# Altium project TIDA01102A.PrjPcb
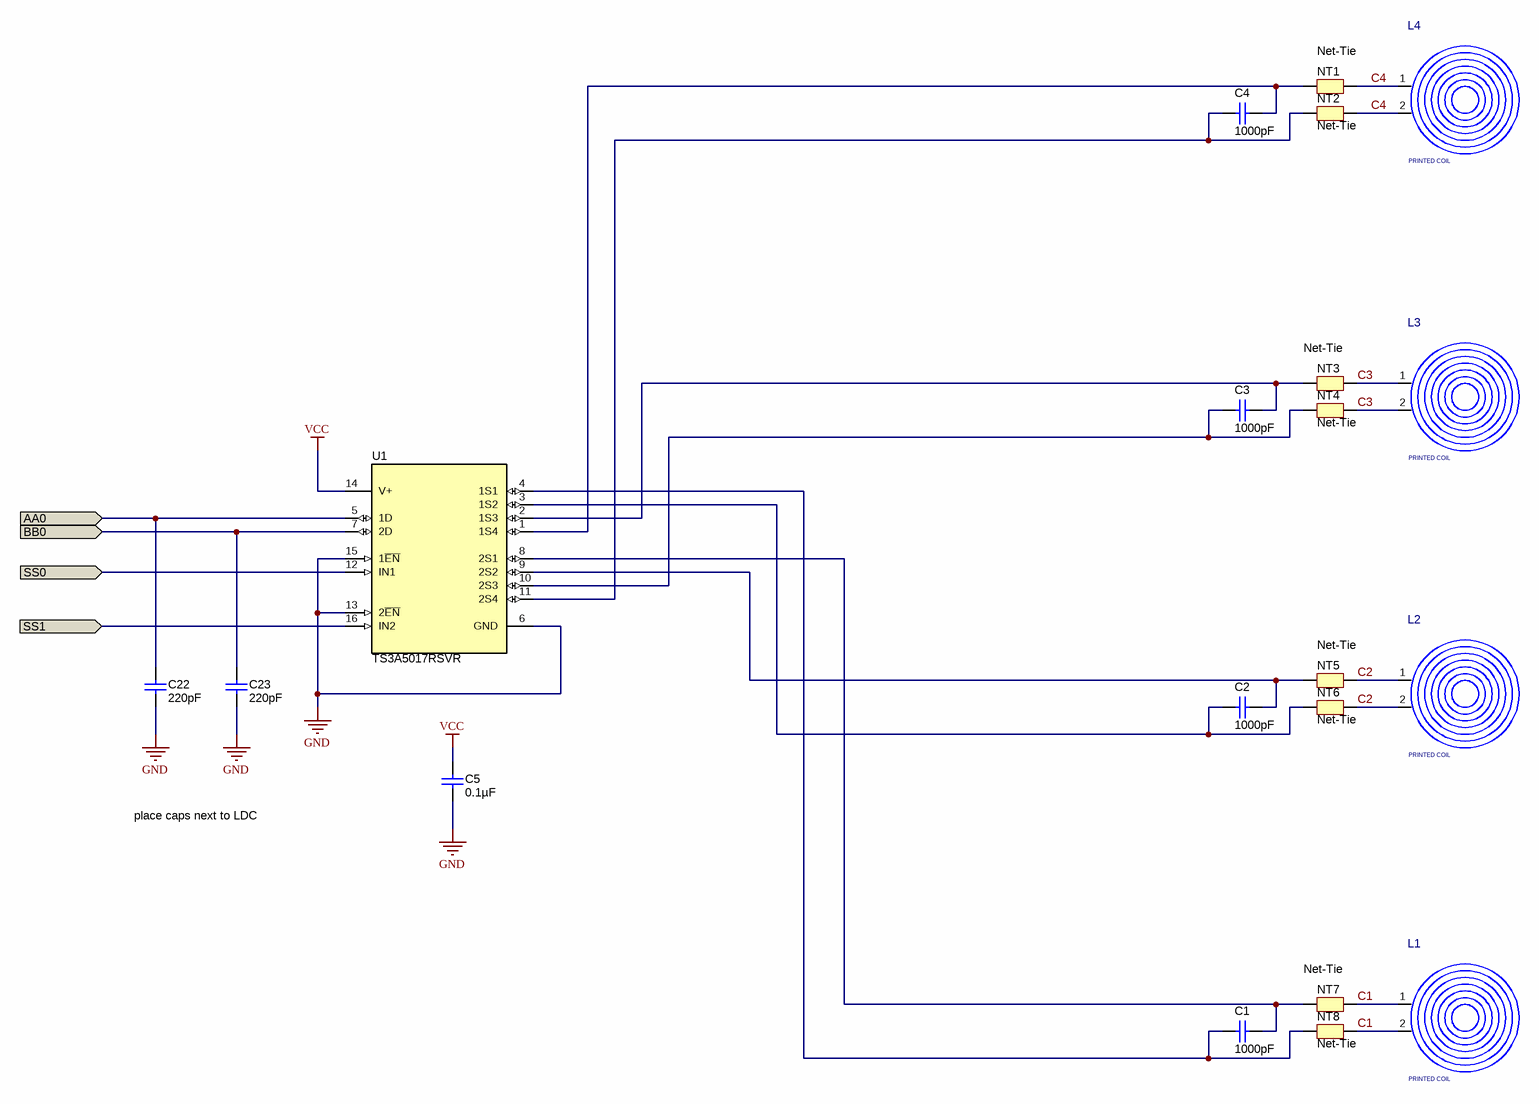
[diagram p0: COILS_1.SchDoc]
TID: TIDA-01102; TechSupport: http://www.ti.com/support; SCH_Rev: A; PRJ_Title: TOM 16 button; PRJ_Number: TIDA-01102; PRJ_Engineer: L. Lapointe; PRJ_Customer: For Public Release; PCB_Rev: A; PCB_Layout: K. Clanin; CopyrightYear: 2016
9 sheets, 177 parts. Net scope: flat (ports and power ports of the same name join across sheets).
Board file: TIDA-01102A.PcbDoc
Sheets:
  COILS_1.SchDoc
  COILS_2.SchDoc
  COILS_3.SchDoc
  COILS_4.SchDoc
  LDC_CLOCK.SchDoc
  LED_ARRAY.SchDoc
  UCONTROLLER.SchDoc
  TIDA-01102A_COVER.SchDoc
  TIDA-01102A_Hardware.SchDoc

## Sheet COILS_1.SchDoc
size 431 x 279 mm; Date: Not shown in title block; ApprovedBy: Not shown in title block; CheckedBy: Not shown in title block; Author: Not shown in title block; CompanyName: Not shown in title block; Engineer: Not shown in title block; Organization: Not shown in title block; Address1: Not shown in title block; Address2: Not shown in title block; Address3: Not shown in title block; Address4: Not shown in title block; DocumentNumber: 1; Revision: Use project parameter SCH_Rev; SheetNumber: 5; SheetTotal: 9; PageSetup: Record=PageOptions¦CenterHorizontal=True¦CenterVertical=True¦PrintScale=1.00¦XCorrection=1.00¦YCorrection=1.00¦PrintKind=0¦BorderSize=5000000¦LeftOffset=0¦BottomOffset=0¦Orientation=2¦PaperLength=1000¦PaperWidth=1000¦Scale=100¦PaperSource=15¦PrintQuality=600¦MediaType=1¦DitherType=10¦PaperKind=Letter¦PrintScaleMode=1

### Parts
C1  ValueDisplayed: 1000pF  [0402]  (hidden comment: GRM155R71H102KA01D)
C2  ValueDisplayed: 1000pF  [0402]  (hidden comment: GRM155R71H102KA01D)
C3  ValueDisplayed: 1000pF  [0402]  (hidden comment: GRM155R71H102KA01D)
C4  ValueDisplayed: 1000pF  [0402]  (hidden comment: GRM155R71H102KA01D)
C5  ValueDisplayed: 0.1µF  [0402]  (hidden comment: C1005X7R1H104K050BB)
C22  ValueDisplayed: 220pF  [0402]  (hidden comment: GRM155R71H221KA01D)
C23  ValueDisplayed: 220pF  [0402]  (hidden comment: GRM155R71H221KA01D)
L1  PRINTED COIL  [PRINTED_COIL_8.2MM_AIR_HOLE]
L2  PRINTED COIL  [PRINTED_COIL_8.2MM_AIR_HOLE]
L3  PRINTED COIL  [PRINTED_COIL_8.2MM_AIR_HOLE]
L4  PRINTED COIL  [PRINTED_COIL_8.2MM_AIR_HOLE]
NT1  Net-Tie  [Net-Tie_10mil]  (net tie, no BOM)
NT2  Net-Tie  [Net-Tie_10mil]  (net tie, no BOM)
NT3  Net-Tie  [Net-Tie_10mil]  (net tie, no BOM)
NT4  Net-Tie  [Net-Tie_10mil]  (net tie, no BOM)
NT5  Net-Tie  [Net-Tie_10mil]  (net tie, no BOM)
NT6  Net-Tie  [Net-Tie_10mil]  (net tie, no BOM)
NT7  Net-Tie  [Net-Tie_10mil]  (net tie, no BOM)
NT8  Net-Tie  [Net-Tie_10mil]  (net tie, no BOM)
U1  TS3A5017RSVR  [RSV0016A]

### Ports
AA0 (in), BB0 (in), SS0 (in), SS1 (in)

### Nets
GND: C5.2 C22.1 C23.1 U1.6(GND) U1.13(2~{EN}) U1.15(1~{EN})
VCC: C5.1 U1.14(V+)
AA0: C22.2 U1.5(1D) ; port AA0
BB0: C23.2 U1.7(2D) ; port BB0
C1: L1.1(.) L1.2(.) NT7.2 NT8.2
C2: L2.1(.) L2.2(.) NT5.2 NT6.2
C3: L3.1(.) L3.2(.) NT3.2 NT4.2
C4: L4.1(.) L4.2(.) NT1.2 NT2.2
SS0: U1.12(IN1) ; port SS0
SS1: U1.16(IN2) ; port SS1
NetC1_1: C1.1 NT8.1 U1.4(1S1)
NetC1_2: C1.2 NT7.1 U1.8(2S1)
NetC2_1: C2.1 NT6.1 U1.3(1S2)
NetC2_2: C2.2 NT5.1 U1.9(2S2)
NetC3_1: C3.1 NT4.1 U1.10(2S3)
NetC3_2: C3.2 NT3.1 U1.2(1S3)
NetC4_1: C4.1 NT2.1 U1.11(2S4)
NetC4_2: C4.2 NT1.1 U1.1(1S4)

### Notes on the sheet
- place caps next to LDC

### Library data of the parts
C1-C4 = GRM155R71H102KA01D: CAP, CERM, 1000 pF, 50 V, +/- 10%, X7R, 0402; Manufacturer: MuRata; Polarized: N; CompType: Capacitor; Value: 1000pF; U/M: EA; Cap_F: 0.000000001; Tolerance_%: 10; Value1: Unknown; VDC_V: 50; Value2: 50V; TaMin_C: -55; TaMax_C: 125; AEC Category: Q200; SizeArea_mm2: 0.5; SizeAreaWB_mm2: 3; SizeX_mm: 1; SizeZ_mm: 0.6
C5 = C1005X7R1H104K050BB: CAP, CERM, 0.1 µF, 50 V, +/- 10%, X7R, 0402; Manufacturer: TDK; Polarized: N; CompType: Capacitor; U/M: EA; Cap_F: 0.0000001; Tolerance_%: 10; ESR_ohm: 0.039064; VDC_V: 50; IRMS_A: 0.814669; TaMin_C: -55; TaMax_C: 125; Value: 0.1uF; Value1: 0.039064 ohm; Value2: 50V; AEC Category: Q200; SizeArea_mm2: 0.5; SizeAreaWB_mm2: 3; SizeX_mm: 1; SizeZ_mm: 0.6
C22 C23 = GRM155R71H221KA01D: CAP, CERM, 220 pF, 50 V, +/- 10%, X7R, 0402; Manufacturer: MuRata; Polarized: N; CompType: Capacitor; Value: 220pF; U/M: EA; Cap_F: 0.00000000022; Tolerance_%: 10; Value1: Unknown; VDC_V: 50; Value2: 50V; TaMin_C: -55; TaMax_C: 125; AEC Category: Q200; SizeArea_mm2: 0.5; SizeAreaWB_mm2: 3; SizeX_mm: 1; SizeZ_mm: 0.6
L1-L4 = PRINTED COIL: 8.2MM 2-layer Coil 3.5uH
NT1-NT8 = Net-Tie: Single point connection between nets.; SymbolCreator: codlsc
U1 = TS3A5017RSVR: 14-Ohm Dual SP4T Analog Switch 3.3-V/2.5-V Analog Multiplexer/Demultiplexer, RSV0016A (UQFN-16); Manufacturer: Texas Instruments; SymbolCreator: Altium; CompType: IC; U/M: EA; SizeArea_mm2: 4.68; SizeAreaWB_mm2: 10.08; SizeX_mm: 1.8; SizeY_mm: 2.6; SizeZ_mm: 0.55

## Sheet COILS_2.SchDoc
size 431 x 279 mm; Date: Not shown in title block; ApprovedBy: Not shown in title block; CheckedBy: Not shown in title block; Author: Not shown in title block; CompanyName: Not shown in title block; Engineer: Not shown in title block; Organization: Not shown in title block; Address1: Not shown in title block; Address2: Not shown in title block; Address3: Not shown in title block; Address4: Not shown in title block; DocumentNumber: 1; Revision: Use project parameter SCH_Rev; SheetNumber: 6; SheetTotal: 9; PageSetup: Record=PageOptions¦CenterHorizontal=True¦CenterVertical=True¦PrintScale=1.00¦XCorrection=1.00¦YCorrection=1.00¦PrintKind=0¦BorderSize=5000000¦LeftOffset=0¦BottomOffset=0¦Orientation=2¦PaperLength=1000¦PaperWidth=1000¦Scale=100¦PaperSource=15¦PrintQuality=600¦MediaType=1¦DitherType=10¦PaperKind=Letter¦PrintScaleMode=1
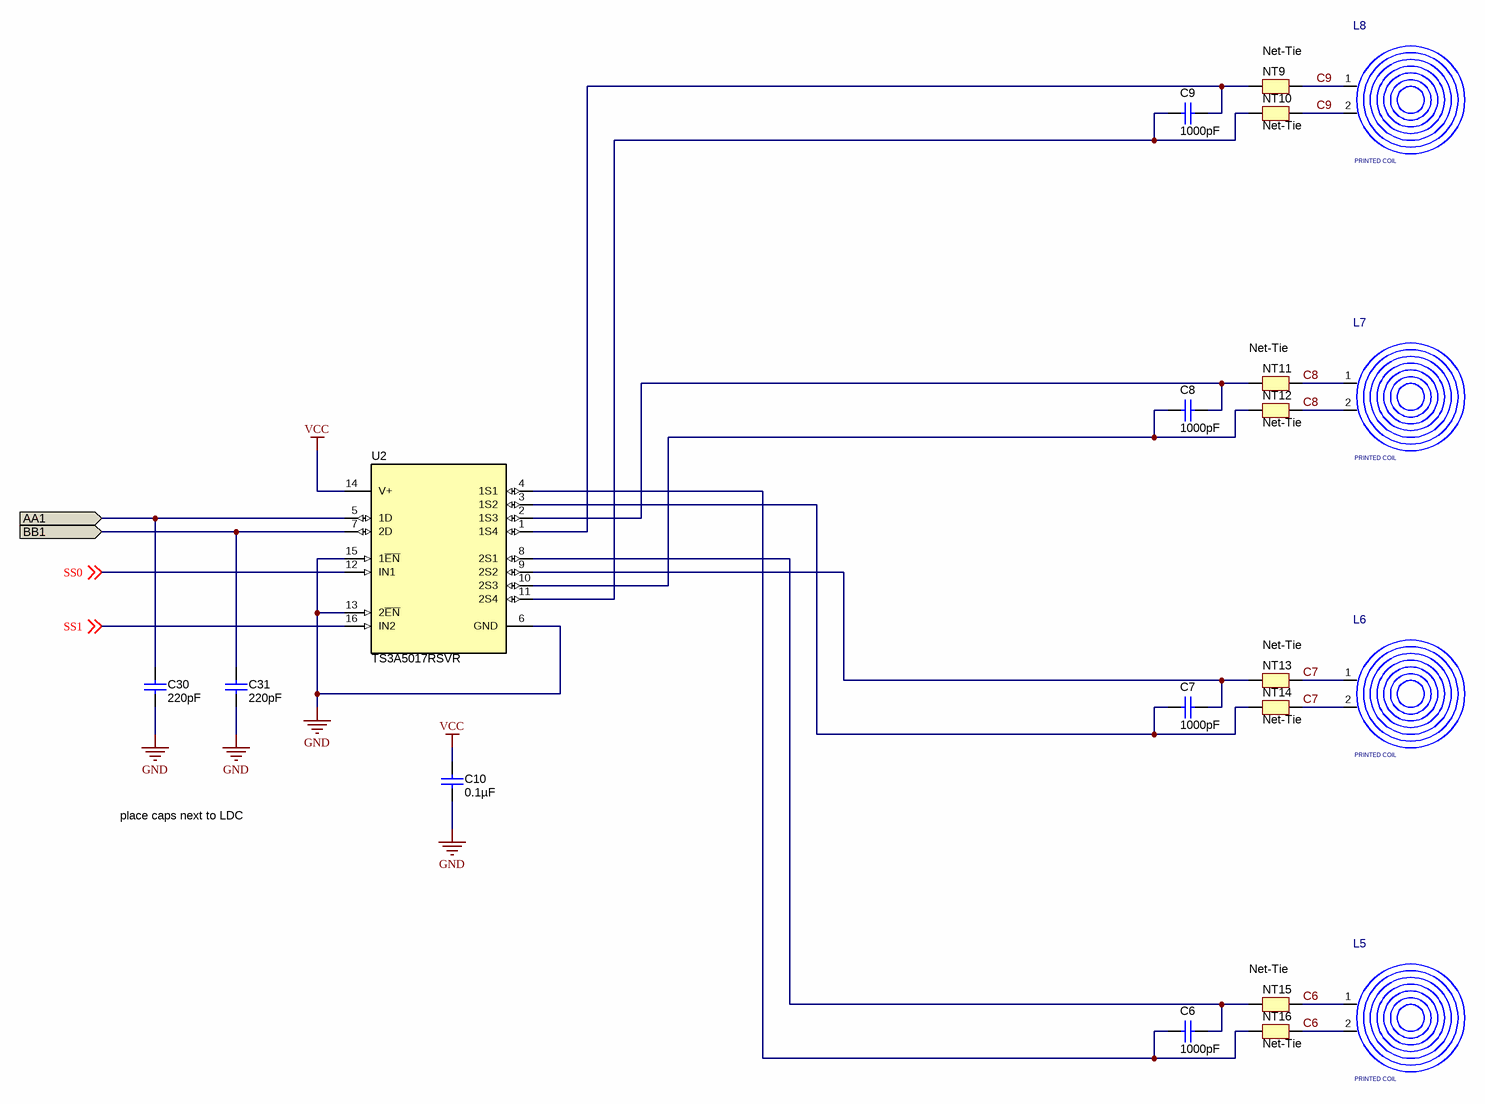
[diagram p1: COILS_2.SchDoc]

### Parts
C6  ValueDisplayed: 1000pF  [0402]  (hidden comment: GRM155R71H102KA01D)
C7  ValueDisplayed: 1000pF  [0402]  (hidden comment: GRM155R71H102KA01D)
C8  ValueDisplayed: 1000pF  [0402]  (hidden comment: GRM155R71H102KA01D)
C9  ValueDisplayed: 1000pF  [0402]  (hidden comment: GRM155R71H102KA01D)
C10  ValueDisplayed: 0.1µF  [0402]  (hidden comment: C1005X7R1H104K050BB)
C30  ValueDisplayed: 220pF  [0402]  (hidden comment: GRM155R71H221KA01D)
C31  ValueDisplayed: 220pF  [0402]  (hidden comment: GRM155R71H221KA01D)
L5  PRINTED COIL  [PRINTED_COIL_8.2MM_AIR_HOLE]
L6  PRINTED COIL  [PRINTED_COIL_8.2MM_AIR_HOLE]
L7  PRINTED COIL  [PRINTED_COIL_8.2MM_AIR_HOLE]
L8  PRINTED COIL  [PRINTED_COIL_8.2MM_AIR_HOLE]
NT9  Net-Tie  [Net-Tie_10mil]  (net tie, no BOM)
NT10  Net-Tie  [Net-Tie_10mil]  (net tie, no BOM)
NT11  Net-Tie  [Net-Tie_10mil]  (net tie, no BOM)
NT12  Net-Tie  [Net-Tie_10mil]  (net tie, no BOM)
NT13  Net-Tie  [Net-Tie_10mil]  (net tie, no BOM)
NT14  Net-Tie  [Net-Tie_10mil]  (net tie, no BOM)
NT15  Net-Tie  [Net-Tie_10mil]  (net tie, no BOM)
NT16  Net-Tie  [Net-Tie_10mil]  (net tie, no BOM)
U2  TS3A5017RSVR  [RSV0016A]

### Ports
AA1 (in), BB1 (in)

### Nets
GND: C10.2 C30.1 C31.1 U2.6(GND) U2.13(2~{EN}) U2.15(1~{EN})
VCC: C10.1 U2.14(V+)
AA1: C30.2 U2.5(1D) ; port AA1
BB1: C31.2 U2.7(2D) ; port BB1
C6: L5.1(.) L5.2(.) NT15.2 NT16.2
C7: L6.1(.) L6.2(.) NT13.2 NT14.2
C8: L7.1(.) L7.2(.) NT11.2 NT12.2
C9: L8.1(.) L8.2(.) NT9.2 NT10.2
SS0: U2.12(IN1) ; off-sheet SS0
SS1: U2.16(IN2) ; off-sheet SS1
NetC6_1: C6.1 NT16.1 U2.4(1S1)
NetC6_2: C6.2 NT15.1 U2.8(2S1)
NetC7_1: C7.1 NT14.1 U2.3(1S2)
NetC7_2: C7.2 NT13.1 U2.9(2S2)
NetC8_1: C8.1 NT12.1 U2.10(2S3)
NetC8_2: C8.2 NT11.1 U2.2(1S3)
NetC9_1: C9.1 NT10.1 U2.11(2S4)
NetC9_2: C9.2 NT9.1 U2.1(1S4)

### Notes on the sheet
- place caps next to LDC

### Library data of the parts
C6-C9 = GRM155R71H102KA01D: as C1 on sheet COILS_1
C10 = C1005X7R1H104K050BB: as C5 on sheet COILS_1
C30 C31 = GRM155R71H221KA01D: as C22 on sheet COILS_1
L5-L8 = PRINTED COIL: 8.2MM 2-layer Coil 3.5uH
NT9-NT16 = Net-Tie: as NT1 on sheet COILS_1
U2 = TS3A5017RSVR: as U1 on sheet COILS_1

## Sheet COILS_3.SchDoc
size 431 x 279 mm; Date: Not shown in title block; ApprovedBy: Not shown in title block; CheckedBy: Not shown in title block; Author: Not shown in title block; CompanyName: Not shown in title block; Engineer: Not shown in title block; Organization: Not shown in title block; Address1: Not shown in title block; Address2: Not shown in title block; Address3: Not shown in title block; Address4: Not shown in title block; DocumentNumber: 1; Revision: Use project parameter SCH_Rev; SheetNumber: 7; SheetTotal: 9; PageSetup: Record=PageOptions¦CenterHorizontal=True¦CenterVertical=True¦PrintScale=1.00¦XCorrection=1.00¦YCorrection=1.00¦PrintKind=0¦BorderSize=5000000¦LeftOffset=0¦BottomOffset=0¦Orientation=2¦PaperLength=1000¦PaperWidth=1000¦Scale=100¦PaperSource=15¦PrintQuality=600¦MediaType=1¦DitherType=10¦PaperKind=Letter¦PrintScaleMode=1
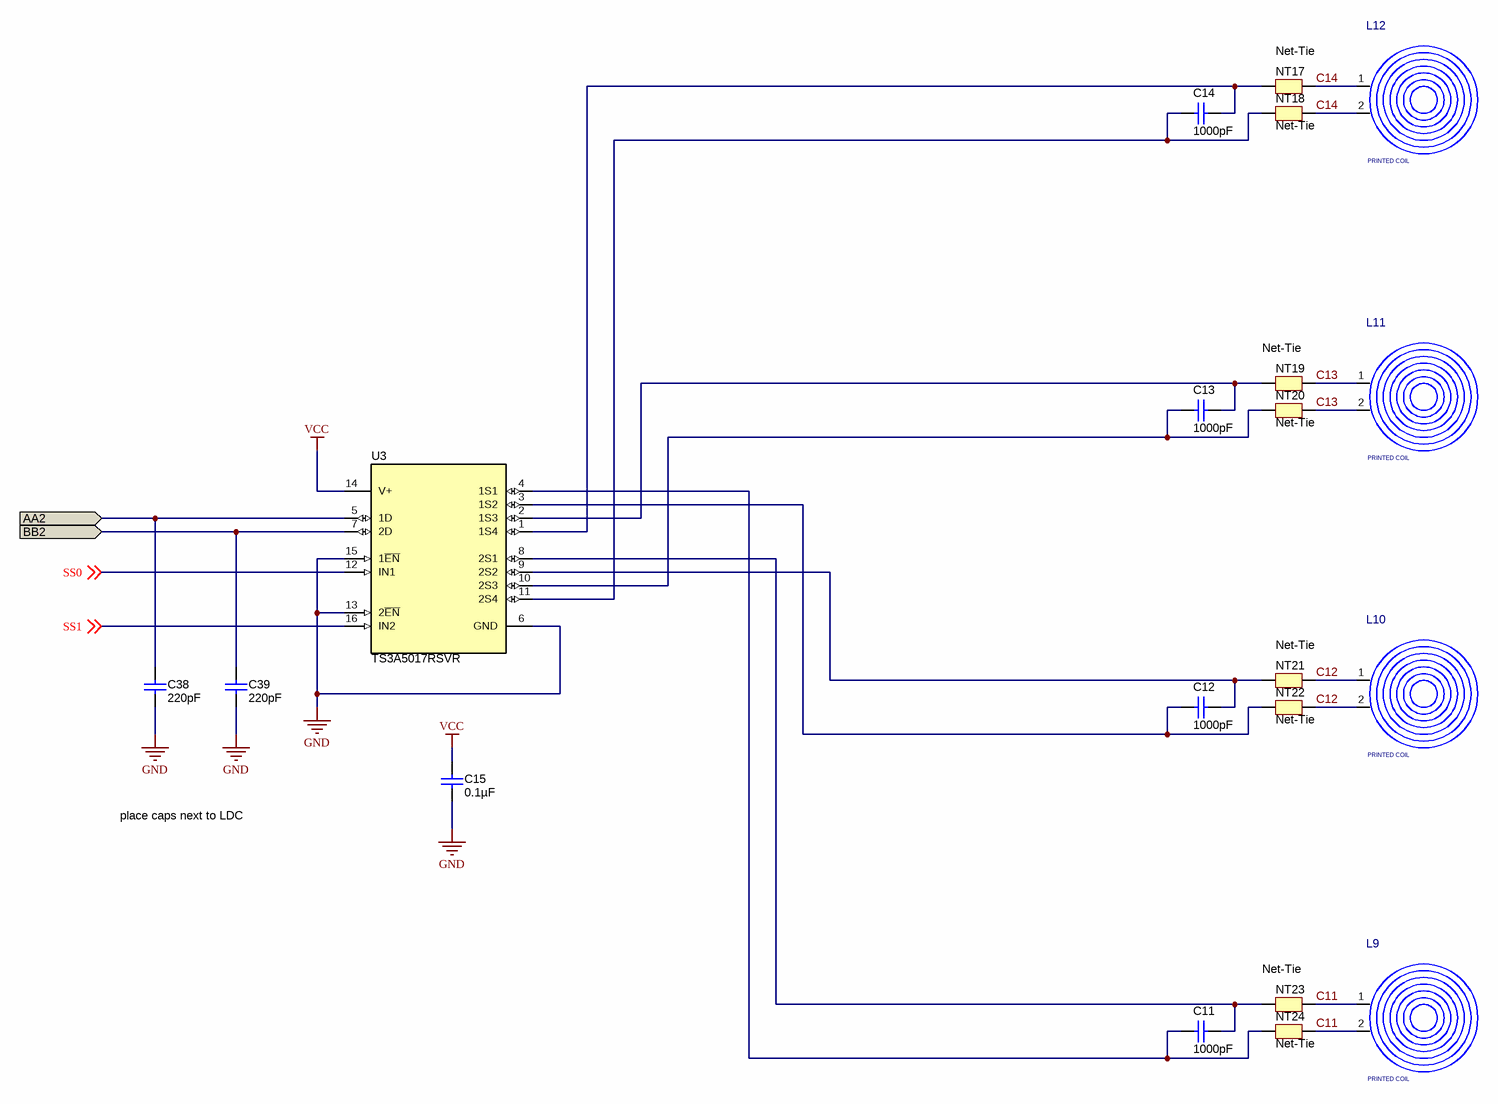
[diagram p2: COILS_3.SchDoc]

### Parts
C11  ValueDisplayed: 1000pF  [0402]  (hidden comment: GRM155R71H102KA01D)
C12  ValueDisplayed: 1000pF  [0402]  (hidden comment: GRM155R71H102KA01D)
C13  ValueDisplayed: 1000pF  [0402]  (hidden comment: GRM155R71H102KA01D)
C14  ValueDisplayed: 1000pF  [0402]  (hidden comment: GRM155R71H102KA01D)
C15  ValueDisplayed: 0.1µF  [0402]  (hidden comment: C1005X7R1H104K050BB)
C38  ValueDisplayed: 220pF  [0402]  (hidden comment: GRM155R71H221KA01D)
C39  ValueDisplayed: 220pF  [0402]  (hidden comment: GRM155R71H221KA01D)
L9  PRINTED COIL  [PRINTED_COIL_8.2MM_AIR_HOLE]
L10  PRINTED COIL  [PRINTED_COIL_8.2MM_AIR_HOLE]
L11  PRINTED COIL  [PRINTED_COIL_8.2MM_AIR_HOLE]
L12  PRINTED COIL  [PRINTED_COIL_8.2MM_AIR_HOLE]
NT17  Net-Tie  [Net-Tie_10mil]  (net tie, no BOM)
NT18  Net-Tie  [Net-Tie_10mil]  (net tie, no BOM)
NT19  Net-Tie  [Net-Tie_10mil]  (net tie, no BOM)
NT20  Net-Tie  [Net-Tie_10mil]  (net tie, no BOM)
NT21  Net-Tie  [Net-Tie_10mil]  (net tie, no BOM)
NT22  Net-Tie  [Net-Tie_10mil]  (net tie, no BOM)
NT23  Net-Tie  [Net-Tie_10mil]  (net tie, no BOM)
NT24  Net-Tie  [Net-Tie_10mil]  (net tie, no BOM)
U3  TS3A5017RSVR  [RSV0016A]

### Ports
AA2 (in), BB2 (in)

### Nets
GND: C15.2 C38.1 C39.1 U3.6(GND) U3.13(2~{EN}) U3.15(1~{EN})
VCC: C15.1 U3.14(V+)
AA2: C38.2 U3.5(1D) ; port AA2
BB2: C39.2 U3.7(2D) ; port BB2
C11: L9.1(.) L9.2(.) NT23.2 NT24.2
C12: L10.1(.) L10.2(.) NT21.2 NT22.2
C13: L11.1(.) L11.2(.) NT19.2 NT20.2
C14: L12.1(.) L12.2(.) NT17.2 NT18.2
SS0: U3.12(IN1) ; off-sheet SS0
SS1: U3.16(IN2) ; off-sheet SS1
NetC11_1: C11.1 NT24.1 U3.4(1S1)
NetC11_2: C11.2 NT23.1 U3.8(2S1)
NetC12_1: C12.1 NT22.1 U3.3(1S2)
NetC12_2: C12.2 NT21.1 U3.9(2S2)
NetC13_1: C13.1 NT20.1 U3.10(2S3)
NetC13_2: C13.2 NT19.1 U3.2(1S3)
NetC14_1: C14.1 NT18.1 U3.11(2S4)
NetC14_2: C14.2 NT17.1 U3.1(1S4)

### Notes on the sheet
- place caps next to LDC

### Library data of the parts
C11-C14 = GRM155R71H102KA01D: as C1 on sheet COILS_1
C15 = C1005X7R1H104K050BB: as C5 on sheet COILS_1
C38 C39 = GRM155R71H221KA01D: as C22 on sheet COILS_1
L9-L12 = PRINTED COIL: 8.2MM 2-layer Coil 3.5uH
NT17-NT24 = Net-Tie: as NT1 on sheet COILS_1
U3 = TS3A5017RSVR: as U1 on sheet COILS_1

## Sheet COILS_4.SchDoc
size 431 x 279 mm; Date: Not shown in title block; ApprovedBy: Not shown in title block; CheckedBy: Not shown in title block; Author: Not shown in title block; CompanyName: Not shown in title block; Engineer: Not shown in title block; Organization: Not shown in title block; Address1: Not shown in title block; Address2: Not shown in title block; Address3: Not shown in title block; Address4: Not shown in title block; DocumentNumber: 1; Revision: Use project parameter SCH_Rev; SheetNumber: 8; SheetTotal: 9; PageSetup: Record=PageOptions¦CenterHorizontal=True¦CenterVertical=True¦PrintScale=1.00¦XCorrection=1.00¦YCorrection=1.00¦PrintKind=0¦BorderSize=5000000¦LeftOffset=0¦BottomOffset=0¦Orientation=2¦PaperLength=1000¦PaperWidth=1000¦Scale=100¦PaperSource=15¦PrintQuality=600¦MediaType=1¦DitherType=10¦PaperKind=Letter¦PrintScaleMode=1
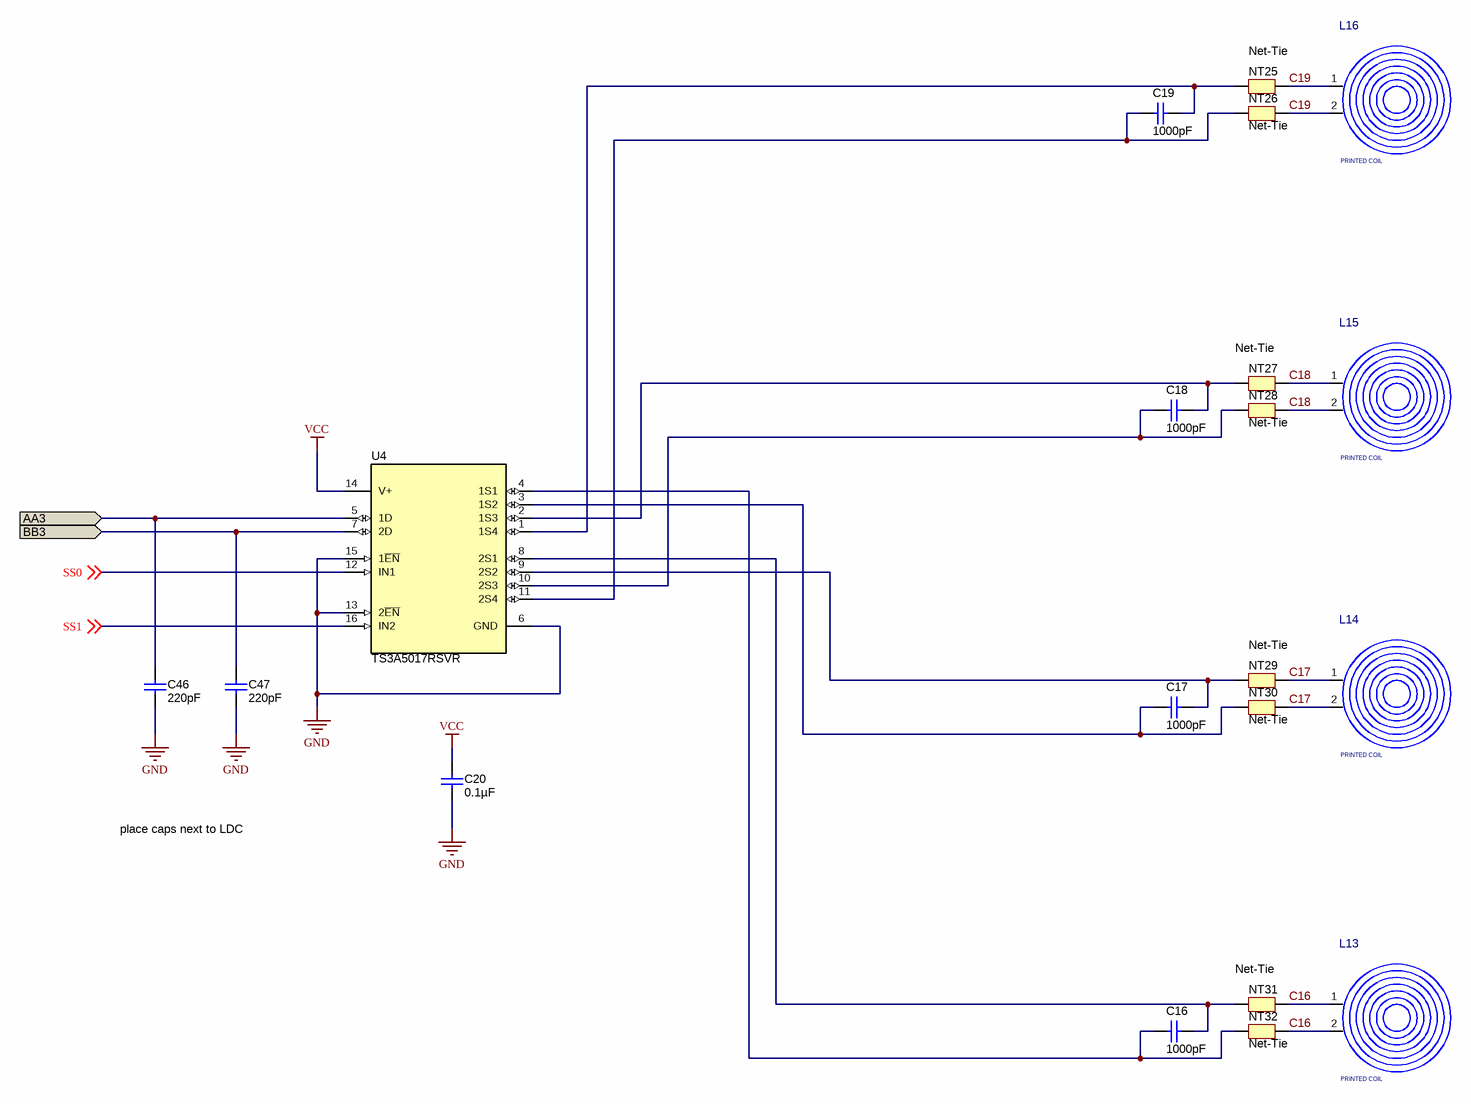
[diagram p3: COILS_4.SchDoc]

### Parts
C16  ValueDisplayed: 1000pF  [0402]  (hidden comment: GRM155R71H102KA01D)
C17  ValueDisplayed: 1000pF  [0402]  (hidden comment: GRM155R71H102KA01D)
C18  ValueDisplayed: 1000pF  [0402]  (hidden comment: GRM155R71H102KA01D)
C19  ValueDisplayed: 1000pF  [0402]  (hidden comment: GRM155R71H102KA01D)
C20  ValueDisplayed: 0.1µF  [0402]  (hidden comment: C1005X7R1H104K050BB)
C46  ValueDisplayed: 220pF  [0402]  (hidden comment: GRM155R71H221KA01D)
C47  ValueDisplayed: 220pF  [0402]  (hidden comment: GRM155R71H221KA01D)
L13  PRINTED COIL  [PRINTED_COIL_8.2MM_AIR_HOLE]
L14  PRINTED COIL  [PRINTED_COIL_8.2MM_AIR_HOLE]
L15  PRINTED COIL  [PRINTED_COIL_8.2MM_AIR_HOLE]
L16  PRINTED COIL  [PRINTED_COIL_8.2MM_AIR_HOLE]
NT25  Net-Tie  [Net-Tie_10mil]  (net tie, no BOM)
NT26  Net-Tie  [Net-Tie_10mil]  (net tie, no BOM)
NT27  Net-Tie  [Net-Tie_10mil]  (net tie, no BOM)
NT28  Net-Tie  [Net-Tie_10mil]  (net tie, no BOM)
NT29  Net-Tie  [Net-Tie_10mil]  (net tie, no BOM)
NT30  Net-Tie  [Net-Tie_10mil]  (net tie, no BOM)
NT31  Net-Tie  [Net-Tie_10mil]  (net tie, no BOM)
NT32  Net-Tie  [Net-Tie_10mil]  (net tie, no BOM)
U4  TS3A5017RSVR  [RSV0016A]

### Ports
AA3 (in), BB3 (in)

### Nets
GND: C20.2 C46.1 C47.1 U4.6(GND) U4.13(2~{EN}) U4.15(1~{EN})
VCC: C20.1 U4.14(V+)
AA3: C46.2 U4.5(1D) ; port AA3
BB3: C47.2 U4.7(2D) ; port BB3
C16: L13.1(.) L13.2(.) NT31.2 NT32.2
C17: L14.1(.) L14.2(.) NT29.2 NT30.2
C18: L15.1(.) L15.2(.) NT27.2 NT28.2
C19: L16.1(.) L16.2(.) NT25.2 NT26.2
SS0: U4.12(IN1) ; off-sheet SS0
SS1: U4.16(IN2) ; off-sheet SS1
NetC16_1: C16.1 NT32.1 U4.4(1S1)
NetC16_2: C16.2 NT31.1 U4.8(2S1)
NetC17_1: C17.1 NT30.1 U4.3(1S2)
NetC17_2: C17.2 NT29.1 U4.9(2S2)
NetC18_1: C18.1 NT28.1 U4.10(2S3)
NetC18_2: C18.2 NT27.1 U4.2(1S3)
NetC19_1: C19.1 NT26.1 U4.11(2S4)
NetC19_2: C19.2 NT25.1 U4.1(1S4)

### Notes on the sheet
- place caps next to LDC

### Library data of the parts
C16-C19 = GRM155R71H102KA01D: as C1 on sheet COILS_1
C20 = C1005X7R1H104K050BB: as C5 on sheet COILS_1
C46 C47 = GRM155R71H221KA01D: as C22 on sheet COILS_1
L13-L16 = PRINTED COIL: 8.2MM 2-layer Coil 3.5uH
NT25-NT32 = Net-Tie: as NT1 on sheet COILS_1
U4 = TS3A5017RSVR: as U1 on sheet COILS_1

## Sheet LDC_CLOCK.SchDoc
size 431 x 279 mm; Date: Not shown in title block; ApprovedBy: Not shown in title block; CheckedBy: Not shown in title block; Author: Not shown in title block; CompanyName: Not shown in title block; Engineer: Not shown in title block; Organization: Not shown in title block; Address1: Not shown in title block; Address2: Not shown in title block; Address3: Not shown in title block; Address4: Not shown in title block; DocumentNumber: 1; Revision: Use project parameter SCH_Rev; SheetNumber: 3; SheetTotal: 9; PageSetup: Record=PageOptions¦CenterHorizontal=True¦CenterVertical=True¦PrintScale=1.00¦XCorrection=1.00¦YCorrection=1.00¦PrintKind=0¦BorderSize=5000000¦LeftOffset=0¦BottomOffset=0¦Orientation=2¦PaperLength=1000¦PaperWidth=1000¦Scale=100¦PaperSource=15¦PrintQuality=600¦MediaType=1¦DitherType=10¦PaperKind=Letter¦PrintScaleMode=1
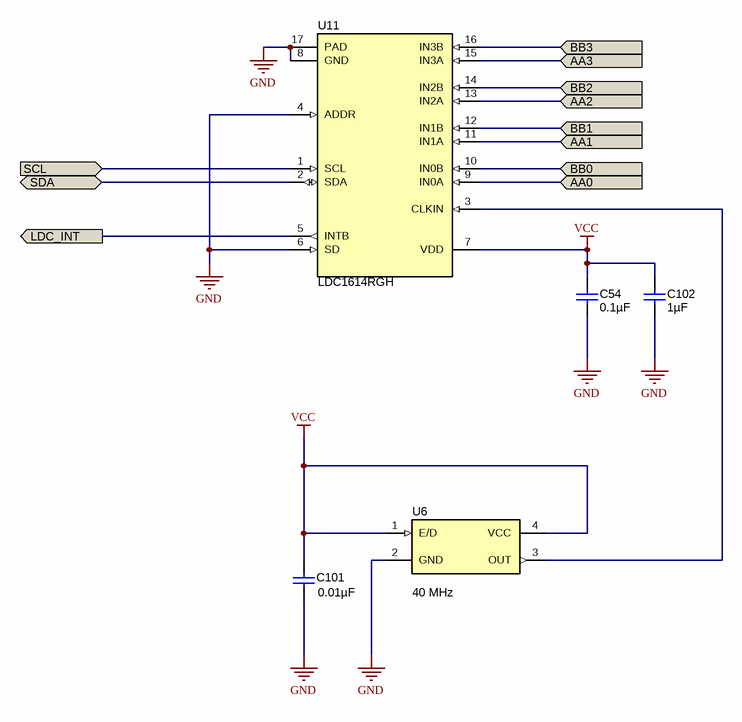
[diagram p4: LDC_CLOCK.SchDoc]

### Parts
C54  ValueDisplayed: 0.1µF  [0402]  (hidden comment: GRM155R71C104KA88D)
C101  ValueDisplayed: 0.01µF  [0402]  (hidden comment: C1005X7R1C103K050BA)
C102  ValueDisplayed: 1µF  [0402]  (hidden comment: GRM155R61A105KE15D)
U6  Frequency: 40 MHz  [OSC_CTS_625]  (hidden comment: 625L3C040M00000)
U11  LDC1614RGH  [RGH0016A]

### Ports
AA0, AA1, AA2, AA3, BB0, BB1, BB2, BB3, LDC_INT (out), SCL (in), SDA (bidir)

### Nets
GND: C54.2 C101.2 C102.1 U6.2(GND) U11.4(ADDR) U11.6(SD) U11.8(GND) U11.17(PAD)
VCC: C54.1 C101.1 C102.2 U6.1(E/D) U6.4(VCC) U11.7(VDD)
AA0: U11.9(IN0A) ; port AA0
AA1: U11.11(IN1A) ; port AA1
AA2: U11.13(IN2A) ; port AA2
AA3: U11.15(IN3A) ; port AA3
BB0: U11.10(IN0B) ; port BB0
BB1: U11.12(IN1B) ; port BB1
BB2: U11.14(IN2B) ; port BB2
BB3: U11.16(IN3B) ; port BB3
LDC_INT: U11.5(INTB) ; port LDC_INT
SCL: U11.1(SCL) ; port SCL
SDA: U11.2(SDA) ; port SDA
NetU6_3: U6.3(OUT) U11.3(CLKIN)

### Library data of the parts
C54 = GRM155R71C104KA88D: CAP, CERM, 0.1 µF, 16 V, +/- 10%, X7R, 0402; Manufacturer: MuRata; Polarized: N; CompType: Capacitor; Value: 0.1uF; U/M: EA; Cap_F: 0.0000001; Tolerance_%: 10; Value1: Unknown; VDC_V: 16; Value2: 16V; TaMin_C: -55; TaMax_C: 125; AEC Category: Q200; SizeArea_mm2: 0.5; SizeAreaWB_mm2: 3; SizeX_mm: 1; SizeZ_mm: 0.6
C101 = C1005X7R1C103K050BA: CAP, CERM, 0.01 µF, 16 V, +/- 10%, X7R, 0402; Manufacturer: TDK; Polarized: N; CompType: Capacitor; Value: 0.01uF; U/M: EA; Cap_F: 0.00000001; Tolerance_%: 10; ESR_ohm: 0.0623; Value1: 0.0623 ohm; VDC_V: 16; Value2: 16V; TaMin_C: -55; TaMax_C: 125; AEC Category: Q200; SizeArea_mm2: 0.5; SizeAreaWB_mm2: 3; SizeX_mm: 1; SizeZ_mm: 0.6
C102 = GRM155R61A105KE15D: CAP, CERM, 1 µF, 10 V, +/- 10%, X5R, 0402; Manufacturer: MuRata; Polarized: N; CompType: Capacitor; Value: 1uF; U/M: EA; Cap_F: 0.000001; Tolerance_%: 10; Value1: Unknown; Value2: 10V; TaMin_C: -55; TaMax_C: 85; AEC Category: Q200; SizeArea_mm2: 0.5; SizeAreaWB_mm2: 3; SizeX_mm: 1; SizeZ_mm: 0.6
U6 = 625L3C040M00000: OSC, 40 MHz, 3.3 V, SMD; Manufacturer: CTS Electrocomponents; SymbolCreator: a0411947; CompType: Oscillator; U/M: EA; TaMin_C: -20; TaMax_C: 70; Frequency Stability: ±50ppm
U11 = LDC1614RGH: Multi-Channel 12/28-Bit Inductance to Digital Converter with I2C, RGH0016A (WQFN-16); Manufacturer: Texas Instruments; SymbolCreator: a0411947; CompType: IC; U/M: EA; SizeArea_mm2: 16; SizeAreaWB_mm2: 25; SizeX_mm: 4; SizeZ_mm: 0.8

## Sheet LED_ARRAY.SchDoc
size 431 x 279 mm; Date: Not shown in title block; ApprovedBy: Not shown in title block; CheckedBy: Not shown in title block; Author: Not shown in title block; CompanyName: Not shown in title block; Engineer: Not shown in title block; Organization: Not shown in title block; Address1: Not shown in title block; Address2: Not shown in title block; Address3: Not shown in title block; Address4: Not shown in title block; DocumentNumber: 1; Revision: Use project parameter SCH_Rev; SheetNumber: 4; SheetTotal: 9; PageSetup: Record=PageOptions¦CenterHorizontal=True¦CenterVertical=True¦PrintScale=0.64¦XCorrection=1.00¦YCorrection=1.00¦PrintKind=0¦BorderSize=5000000¦LeftOffset=0¦BottomOffset=0¦Orientation=2¦PaperLength=1000¦PaperWidth=1000¦Scale=100¦PaperSource=15¦PrintQuality=600¦MediaType=1¦DitherType=10¦PrintScaleMode=1¦PaperKind=11x17¦PaperIndex=17
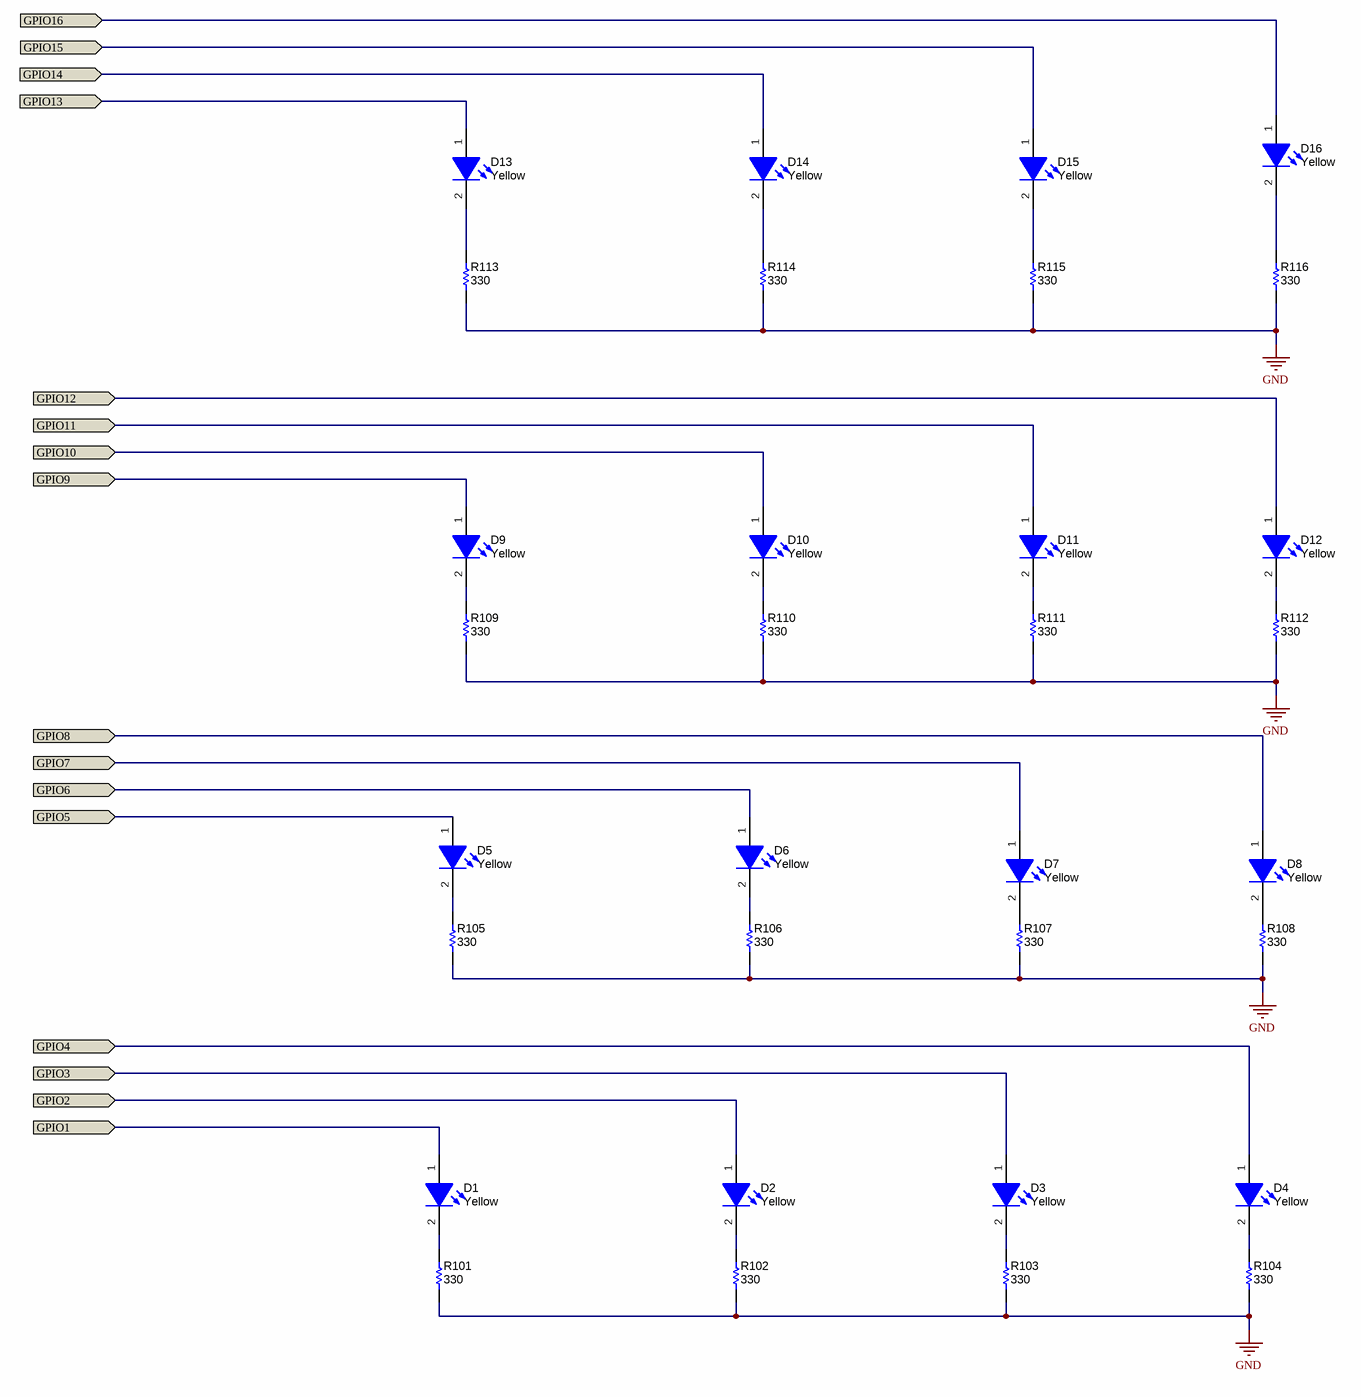
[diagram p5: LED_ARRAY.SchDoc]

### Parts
D1  value Yellow  [LED_LTST-C170]  (hidden comment: LTST-C170KSKT)
D2  value Yellow  [LED_LTST-C170]  (hidden comment: LTST-C170KSKT)
D3  value Yellow  [LED_LTST-C170]  (hidden comment: LTST-C170KSKT)
D4  value Yellow  [LED_LTST-C170]  (hidden comment: LTST-C170KSKT)
D5  value Yellow  [LED_LTST-C170]  (hidden comment: LTST-C170KSKT)
D6  value Yellow  [LED_LTST-C170]  (hidden comment: LTST-C170KSKT)
D7  value Yellow  [LED_LTST-C170]  (hidden comment: LTST-C170KSKT)
D8  value Yellow  [LED_LTST-C170]  (hidden comment: LTST-C170KSKT)
D9  value Yellow  [LED_LTST-C170]  (hidden comment: LTST-C170KSKT)
D10  value Yellow  [LED_LTST-C170]  (hidden comment: LTST-C170KSKT)
D11  value Yellow  [LED_LTST-C170]  (hidden comment: LTST-C170KSKT)
D12  value Yellow  [LED_LTST-C170]  (hidden comment: LTST-C170KSKT)
D13  value Yellow  [LED_LTST-C170]  (hidden comment: LTST-C170KSKT)
D14  value Yellow  [LED_LTST-C170]  (hidden comment: LTST-C170KSKT)
D15  value Yellow  [LED_LTST-C170]  (hidden comment: LTST-C170KSKT)
D16  value Yellow  [LED_LTST-C170]  (hidden comment: LTST-C170KSKT)
R101  ValueDisplayed: 330  [0402]  (hidden comment: CRCW0402330RJNED)
R102  ValueDisplayed: 330  [0402]  (hidden comment: CRCW0402330RJNED)
R103  ValueDisplayed: 330  [0402]  (hidden comment: CRCW0402330RJNED)
R104  ValueDisplayed: 330  [0402]  (hidden comment: CRCW0402330RJNED)
R105  ValueDisplayed: 330  [0402]  (hidden comment: CRCW0402330RJNED)
R106  ValueDisplayed: 330  [0402]  (hidden comment: CRCW0402330RJNED)
R107  ValueDisplayed: 330  [0402]  (hidden comment: CRCW0402330RJNED)
R108  ValueDisplayed: 330  [0402]  (hidden comment: CRCW0402330RJNED)
R109  ValueDisplayed: 330  [0402]  (hidden comment: CRCW0402330RJNED)
R110  ValueDisplayed: 330  [0402]  (hidden comment: CRCW0402330RJNED)
R111  ValueDisplayed: 330  [0402]  (hidden comment: CRCW0402330RJNED)
R112  ValueDisplayed: 330  [0402]  (hidden comment: CRCW0402330RJNED)
R113  ValueDisplayed: 330  [0402]  (hidden comment: CRCW0402330RJNED)
R114  ValueDisplayed: 330  [0402]  (hidden comment: CRCW0402330RJNED)
R115  ValueDisplayed: 330  [0402]  (hidden comment: CRCW0402330RJNED)
R116  ValueDisplayed: 330  [0402]  (hidden comment: CRCW0402330RJNED)

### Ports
GPIO1 (in), GPIO2 (in), GPIO3 (in), GPIO4 (in), GPIO5 (in), GPIO6 (in), GPIO7 (in), GPIO8 (in), GPIO9 (in), GPIO10 (in), GPIO11 (in), GPIO12 (in), GPIO13 (in), GPIO14 (in), GPIO15 (in), GPIO16 (in)

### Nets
GND: R101.1 R102.1 R103.1 R104.1 R105.1 R106.1 R107.1 R108.1 R109.1 R110.1 R111.1 R112.1 R113.1 R114.1 R115.1 R116.1
GPIO1: D1.1(A) ; port GPIO1
GPIO2: D2.1(A) ; port GPIO2
GPIO3: D3.1(A) ; port GPIO3
GPIO4: D4.1(A) ; port GPIO4
GPIO5: D5.1(A) ; port GPIO5
GPIO6: D6.1(A) ; port GPIO6
GPIO7: D7.1(A) ; port GPIO7
GPIO8: D8.1(A) ; port GPIO8
GPIO9: D9.1(A) ; port GPIO9
GPIO10: D10.1(A) ; port GPIO10
GPIO11: D11.1(A) ; port GPIO11
GPIO12: D12.1(A) ; port GPIO12
GPIO13: D13.1(A) ; port GPIO13
GPIO14: D14.1(A) ; port GPIO14
GPIO15: D15.1(A) ; port GPIO15
GPIO16: D16.1(A) ; port GPIO16
NetD1_2: D1.2(K) R101.2
NetD2_2: D2.2(K) R102.2
NetD3_2: D3.2(K) R103.2
NetD4_2: D4.2(K) R104.2
NetD5_2: D5.2(K) R105.2
NetD6_2: D6.2(K) R106.2
NetD7_2: D7.2(K) R107.2
NetD8_2: D8.2(K) R108.2
NetD9_2: D9.2(K) R109.2
NetD10_2: D10.2(K) R110.2
NetD11_2: D11.2(K) R111.2
NetD12_2: D12.2(K) R112.2
NetD13_2: D13.2(K) R113.2
NetD14_2: D14.2(K) R114.2
NetD15_2: D15.2(K) R115.2
NetD16_2: D16.2(K) R116.2

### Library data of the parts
D1-D16 = LTST-C170KSKT: LED, Yellow , SMD; Manufacturer: Lite-On; Type: AlInGaP; Vf_V: 2; Value2: 2V; Io_A: 0.02; Value1: W; U/M: EA; SizeAreaWB_mm2: 6.75; SizeArea_mm2: 2.5; SizeY_mm: 1.25; SizeZ_mm: 1.2
R101-R116 = CRCW0402330RJNED: RES, 330, 5%, 0.063 W, 0402; Manufacturer: Vishay-Dale; CompType: Resistor; Value: 330; Value_Code: 330R; Tolerance_%: 5; Power_W: 0.063; Value2: 0.063W; VDC_V: 50; TempCo: 200 ppm/C; EIA_Code: E24; U/M: EA; AEC Category: Q200; SizeArea_mm2: 0.5; SizeX_mm: 1; SizeZ_mm: 0.6

## Sheet UCONTROLLER.SchDoc
size 431 x 279 mm; Date: Not shown in title block; ApprovedBy: Not shown in title block; CheckedBy: Not shown in title block; Author: Not shown in title block; CompanyName: Not shown in title block; Engineer: Not shown in title block; Organization: Not shown in title block; Address1: Not shown in title block; Address2: Not shown in title block; Address3: Not shown in title block; Address4: Not shown in title block; DocumentNumber: 1; Revision: Use project parameter SCH_Rev; SheetNumber: 2; SheetTotal: 9; PageSetup: Record=PageOptions¦CenterHorizontal=True¦CenterVertical=True¦PrintScale=1.00¦XCorrection=1.00¦YCorrection=1.00¦PrintKind=0¦BorderSize=5000000¦LeftOffset=0¦BottomOffset=0¦Orientation=2¦PaperLength=1000¦PaperWidth=1000¦Scale=100¦PaperSource=15¦PrintQuality=600¦MediaType=1¦DitherType=10¦PaperKind=Letter¦PrintScaleMode=1
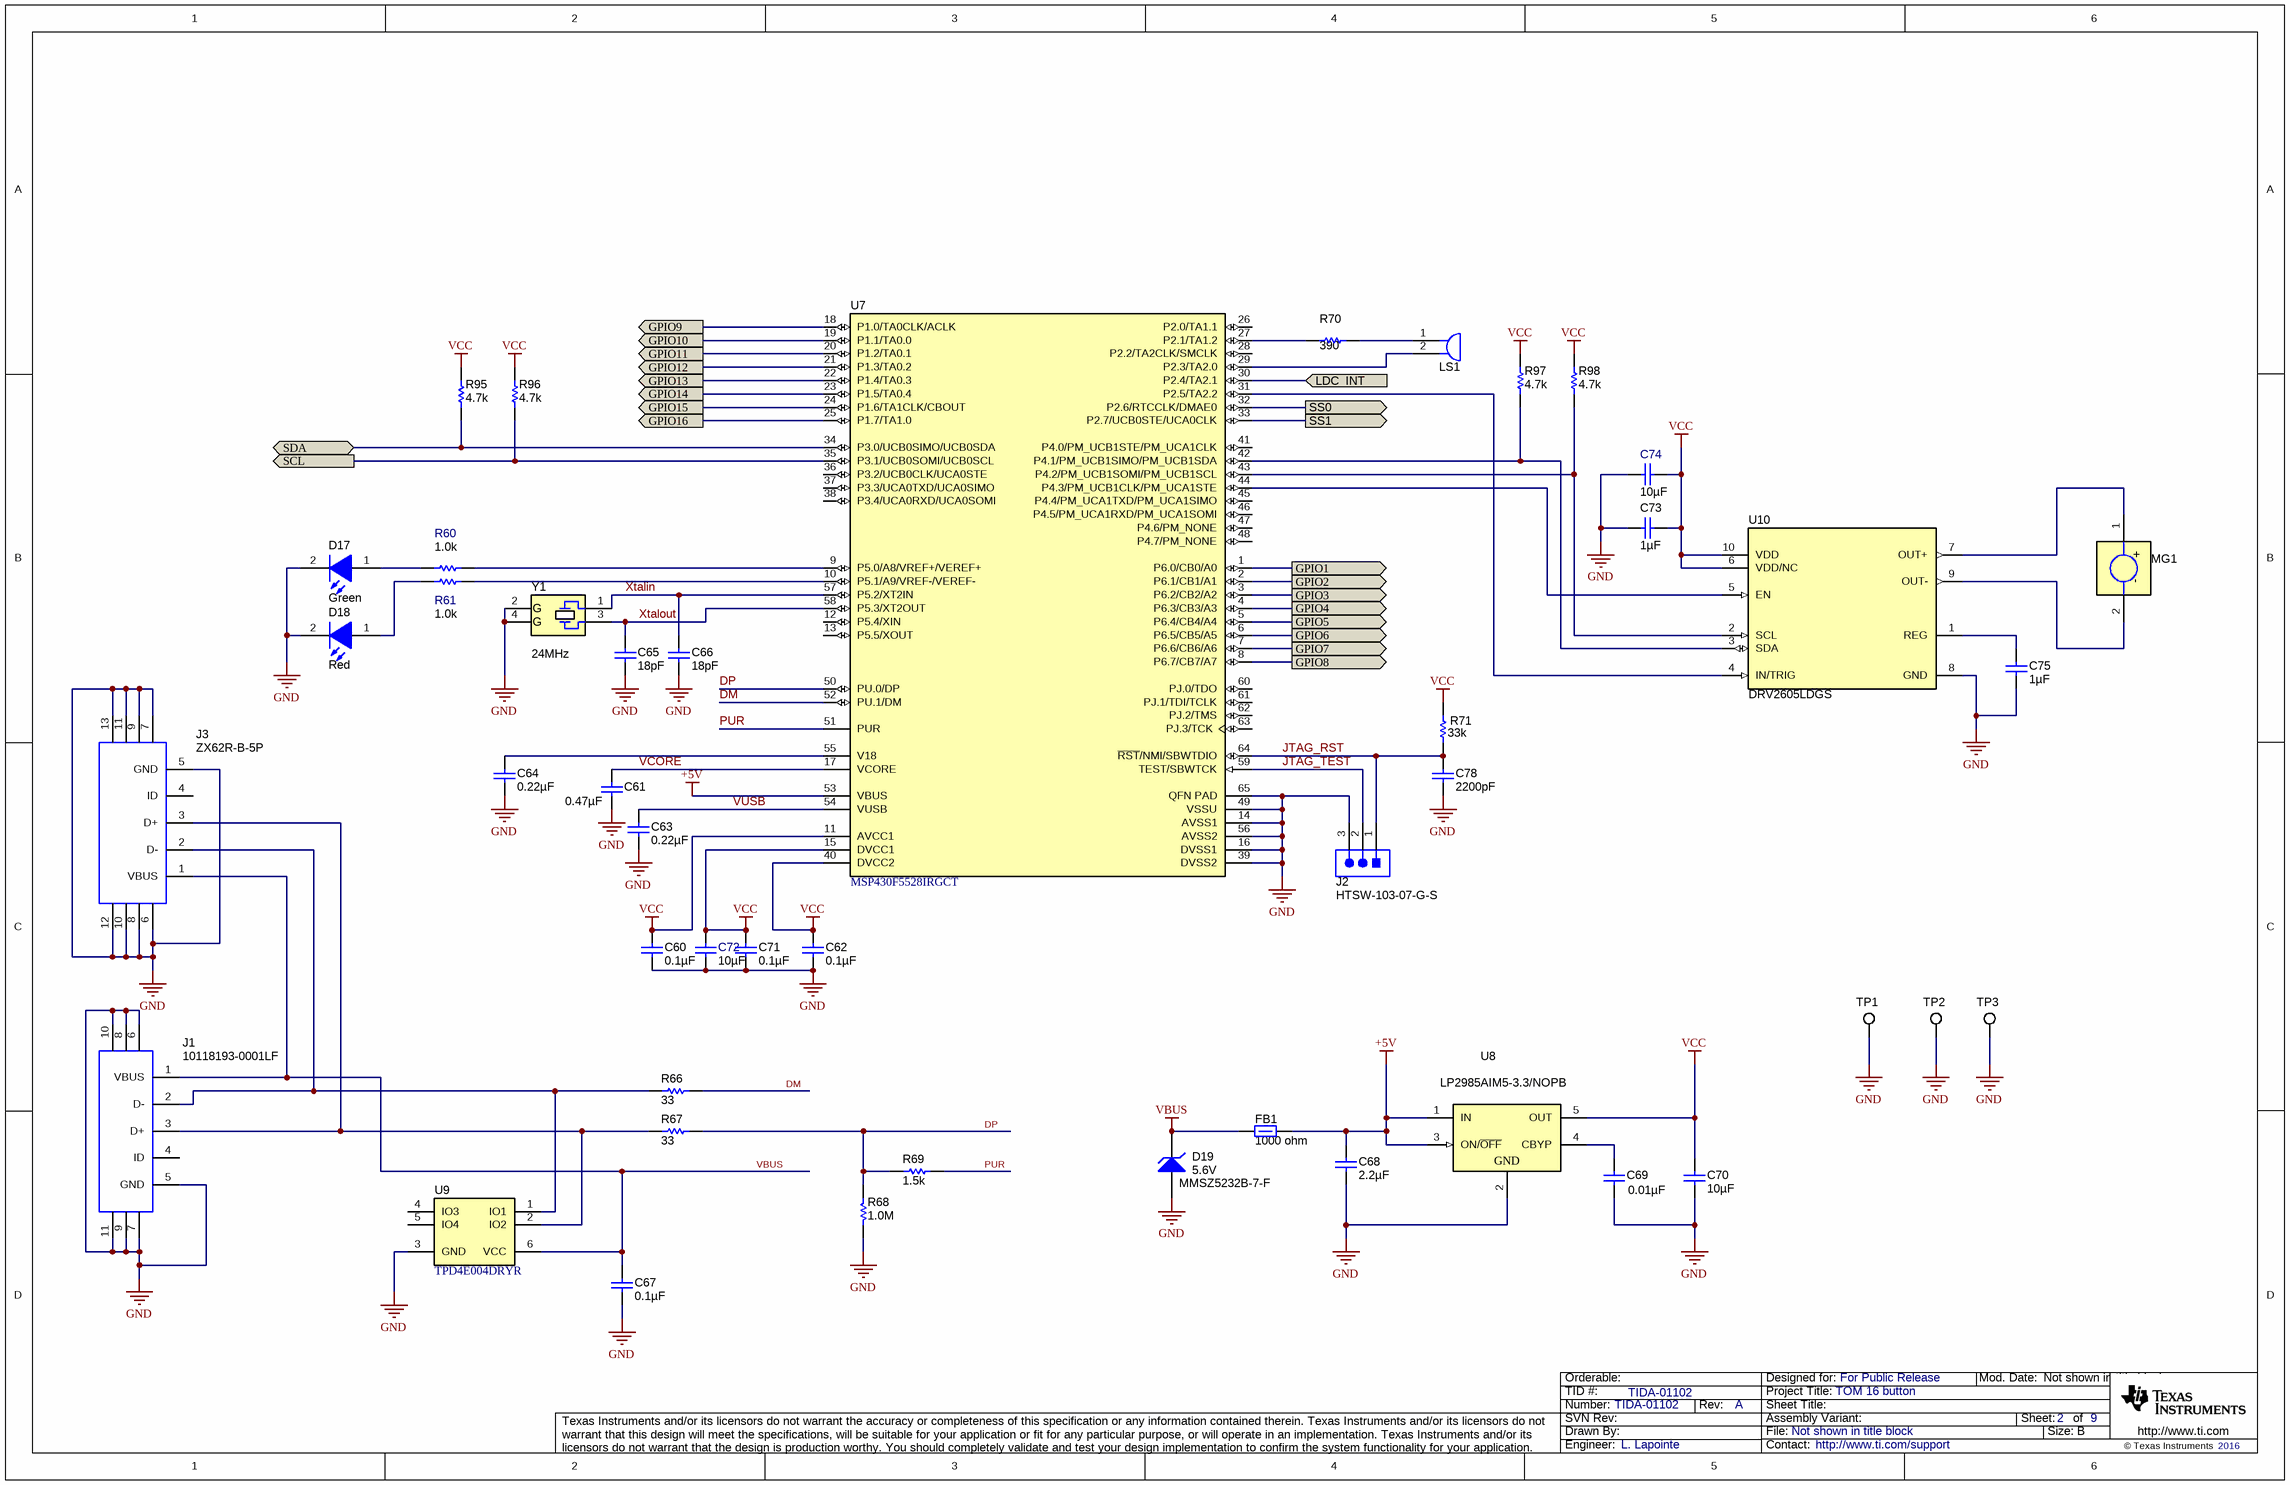
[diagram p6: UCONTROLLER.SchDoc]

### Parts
C60  ValueDisplayed: 0.1µF  [0402]  (hidden comment: C1005X7R1H104K050BB)
C61  ValueDisplayed: 0.47µF  [0603]  (hidden comment: C0603C474K8RACTU)
C62  ValueDisplayed: 0.1µF  [0402]  (hidden comment: C1005X7R1H104K050BB)
C63  ValueDisplayed: 0.22µF  [0402]  (hidden comment: C1005X7R1C224K050BC)
C64  ValueDisplayed: 0.22µF  [0402]  (hidden comment: C1005X7R1C224K050BC)
C65  ValueDisplayed: 18pF  [0402]  (hidden comment: GRM1555C1H180JA01D)
C66  ValueDisplayed: 18pF  [0402]  (hidden comment: GRM1555C1H180JA01D)
C67  ValueDisplayed: 0.1µF  [0402]  (hidden comment: GRM155R71C104KA88D)
C68  ValueDisplayed: 2.2µF  [0603]  (hidden comment: C0603C225K8PACTU)
C69  ValueDisplayed: 0.01µF  [0402]  (hidden comment: C1005X7R1C103K050BA)
C70  ValueDisplayed: 10µF  [0603]  (hidden comment: GRM188R61A106ME69D)
C71  ValueDisplayed: 0.1µF  [0402]  (hidden comment: C1005X7R1H104K050BB)
C72  ValueDisplayed: 10µF  [0603]  (hidden comment: GRM188R61A106ME69D)
C73  ValueDisplayed: 1µF  [0402]  (hidden comment: GRM155R61A105KE15D)
C74  ValueDisplayed: 10µF  [0603]  (hidden comment: GRM188R61A106ME69D)
C75  ValueDisplayed: 1µF  [0402]  (hidden comment: GRM155R61A105KE15D)
C78  ValueDisplayed: 2200pF  [0603]  (hidden comment: C0603X222K5RACTU)
D17  value Green  [LG L29K_GREEN]  (hidden comment: LG L29K-G2J1-24-Z)
D18  value Red  [LS L29K_Red]  (hidden comment: LS L29K-G1J2-1-Z)
D19  MMSZ5232B-7-F  value 5.6V  [SOD-123]
FB1  value 1000 ohm  [MMZ1608_095]  (hidden comment: MMZ1608B102CTA00)
J1  10118193-0001LF  [FCI_10118193-0001LF]
J2  HTSW-103-07-G-S  [Samtec_HTSW-103-07-G-S]
J3  ZX62R-B-5P  [Hirose_ZX62R-B-5P]
LS1  CPT-9019S-SMT-TR  [CPT-9019S]  (value not drawn)
MG1  C10-000  [Precision_C10-000]  (value not drawn)
R60  ValueDisplayed: 1.0k  [0402]  (hidden comment: CRCW04021K00JNED)
R61  ValueDisplayed: 1.0k  [0402]  (hidden comment: CRCW04021K00JNED)
R66  ValueDisplayed: 33  [0402]  (hidden comment: CRCW040233R0JNED)
R67  ValueDisplayed: 33  [0402]  (hidden comment: CRCW040233R0JNED)
R68  ValueDisplayed: 1.0M  [0402]  (hidden comment: CRCW04021M00JNED)
R69  ValueDisplayed: 1.5k  [0402]  (hidden comment: CRCW04021K50JNED)
R70  ValueDisplayed: 390  [0603]  (hidden comment: RC0603FR-07390RL)
R71  value 33k  [0402]  (hidden comment: CRCW040233K0JNED)
R95  ValueDisplayed: 4.7k  [0402]  (hidden comment: CRCW04024K70JNED)
R96  ValueDisplayed: 4.7k  [0402]  (hidden comment: CRCW04024K70JNED)
R97  ValueDisplayed: 4.7k  [0402]  (hidden comment: CRCW04024K70JNED)
R98  ValueDisplayed: 4.7k  [0402]  (hidden comment: CRCW04024K70JNED)
TP1  5015  [Testpoint_Keystone_Miniature]  (value not drawn)
TP2  5015  [Testpoint_Keystone_Miniature]  (value not drawn)
TP3  5015  [Testpoint_Keystone_Miniature]  (value not drawn)
U7  MSP430F5528IRGCT  [RGC0064B]
U8  LP2985AIM5-3.3/NOPB  [MF05A_N]
U9  TPD4E004DRYR  [DRY0006A]
U10  DRV2605LDGS  [DGS0010A_N]
Y1  Frequency: 24MHz  [XTAL_ABM8]  (hidden comment: ABM8-24.000MHZ-B2-T)

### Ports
GPIO1 (out), GPIO2 (out), GPIO3 (out), GPIO4 (out), GPIO5 (out), GPIO6 (out), GPIO7 (out), GPIO8 (out), GPIO9 (out), GPIO10 (out), GPIO11 (out), GPIO12 (out), GPIO13 (out), GPIO14 (out), GPIO15 (out), GPIO16 (out), LDC_INT (in), SCL (out), SDA (bidir), SS0 (out), SS1 (out)

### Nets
+5V: C68.1 FB1.2 U7.53(VBUS) U8.1(IN) U8.3(ON/~{OFF})
GND: C60.2 C61.2 C62.2 C63.2 C64.1 C65.2 C66.2 C67.2 C68.2 C69.2 C70.2 C71.2 C72.2 C73.1 C74.1 C75.1 C78.1 D17.2(K) D18.2(K) D19.2(A) J1.5(GND) J1.6 J1.7 J1.8 J1.9 J1.10 J1.11 J2.3 J3.5(GND) J3.6 J3.7 J3.8 J3.9 J3.10 J3.11 J3.12 J3.13 R68.1 TP1.1 TP2.1 TP3.1 U7.14(AVSS1) U7.16(DVSS1) U7.39(DVSS2) U7.49(VSSU) U7.56(AVSS2) U7.65(QFN_PAD) U8.2(GND) U9.3(GND) U10.8(GND) Y1.2(GND) Y1.4(GND)
VBUS: C67.1 D19.1(K) FB1.1 J1.1(VBUS) J3.1(VBUS) U9.6(VCC)
VCC: C60.1 C62.1 C70.1 C71.1 C72.1 C73.2 C74.2 R71.1 R95.1 R96.1 R97.1 R98.1 U7.11(AVCC1) U7.15(DVCC1) U7.40(DVCC2) U8.5(OUT) U10.6(VDD/NC) U10.10(VDD)
DM: R66.2 U7.52(PU.1/DM)
DP: R67.2 R68.2 R69.2 U7.50(PU.0/DP)
GPIO1: U7.1(P6.0/CB0/A0) ; port GPIO1
GPIO2: U7.2(P6.1/CB1/A1) ; port GPIO2
GPIO3: U7.3(P6.2/CB2/A2) ; port GPIO3
GPIO4: U7.4(P6.3/CB3/A3) ; port GPIO4
GPIO5: U7.5(P6.4/CB4/A4) ; port GPIO5
GPIO6: U7.6(P6.5/CB5/A5) ; port GPIO6
GPIO7: U7.7(P6.6/CB6/A6) ; port GPIO7
GPIO8: U7.8(P6.7/CB7/A7) ; port GPIO8
GPIO9: U7.18(P1.0/TA0CLK/ACLK) ; port GPIO9
GPIO10: U7.19(P1.1/TA0.0) ; port GPIO10
GPIO11: U7.20(P1.2/TA0.1) ; port GPIO11
GPIO12: U7.21(P1.3/TA0.2) ; port GPIO12
GPIO13: U7.22(P1.4/TA0.3) ; port GPIO13
GPIO14: U7.23(P1.5/TA0.4) ; port GPIO14
GPIO15: U7.24(P1.6/TA1CLK/CBOUT) ; port GPIO15
GPIO16: U7.25(P1.7/TA1.0) ; port GPIO16
JTAG_RST: C78.2 J2.1 R71.2 U7.64(~{RST}/NMI/SBWTDIO)
JTAG_TEST: J2.2 U7.59(TEST/SBWTCK)
LDC_INT: U7.30(P2.4/TA2.1) ; port LDC_INT
PUR: R69.1 U7.51(PUR)
SCL: R96.2 U7.35(P3.1/UCB0SOMI/UCB0SCL) ; port SCL
SDA: R95.2 U7.34(P3.0/UCB0SIMO/UCB0SDA) ; port SDA
SS0: U7.32(P2.6/RTCCLK/DMAE0) ; port SS0
SS1: U7.33(P2.7/UCB0STE/UCA0CLK) ; port SS1
VCORE: C61.1 U7.17(VCORE)
VUSB: C63.1 U7.54(VUSB)
Xtalin: C66.1 U7.57(P5.2/XT2IN) Y1.1
Xtalout: C65.1 U7.58(P5.3/XT2OUT) Y1.3
NetC64_2: C64.2 U7.55(V18)
NetC69_1: C69.1 U8.4(CBYP)
NetC75_2: C75.2 U10.1(REG)
NetD17_1: D17.1(A) R60.1
NetD18_1: D18.1(A) R61.1
NetJ1_2: J1.2(D-) J3.2(D-) R66.1 U9.1(IO1)
NetJ1_3: J1.3(D+) J3.3(D+) R67.1 U9.2(IO2)
NetLS1_1: LS1.1 R70.2
NetLS1_2: LS1.2 U7.29(P2.3/TA2.0)
NetMG1_1: MG1.1(+) U10.7(OUT+)
NetMG1_2: MG1.2(-) U10.9(OUT-)
NetR60_2: R60.2 U7.9(P5.0/A8/VREF+/VEREF+)
NetR61_2: R61.2 U7.10(P5.1/A9/VREF-/VEREF-)
NetR70_1: R70.1 U7.27(P2.1/TA1.2)
NetR97_2: R97.2 U7.42(P4.1/PM_UCB1SIMO/PM_UCB1SDA) U10.3(SDA)
NetR98_2: R98.2 U7.43(P4.2/PM_UCB1SOMI/PM_UCB1SCL) U10.2(SCL)
NetU7_31: U7.31(P2.5/TA2.2) U10.4(IN/TRIG)
NetU7_44: U7.44(P4.3/PM_UCB1CLK/PM_UCA1STE) U10.5(EN)

Not connected (* = marked no-connect by the designer): J1 4(ID); J3 4(ID); U7 12(P5.4/XIN) 13(P5.5/XOUT) 26(P2.0/TA1.1) 28(P2.2/TA2CLK/SMCLK) 36(P3.2/UCB0CLK/UCA0STE) 37(P3.3/UCA0TXD/UCA0SIMO) 38(P3.4/UCA0RXD/UCA0SOMI) 41(P4.0/PM_UCB1STE/PM_UCA1CLK) 45(P4.4/PM_UCA1TXD/PM_UCA1SIMO) 46(P4.5/PM_UCA1RXD/PM_UCA1SOMI) 47(P4.6/PM_NONE) 48(P4.7/PM_NONE) 60(PJ.0/TDO) 61(PJ.1/TDI/TCLK) 62(PJ.2/TMS) 63(PJ.3/TCK); U9 4(IO3) 5(IO4)

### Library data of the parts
C60 C62 C71 = C1005X7R1H104K050BB: as C5 on sheet COILS_1
C61 = C0603C474K8RACTU: CAP, CERM, 0.47 µF, 10 V, +/- 10%, X7R, 0603; Manufacturer: Kemet; Polarized: N; CompType: Capacitor; Value: 0.47uF; U/M: EA; Cap_F: 0.00000047; Tolerance_%: 10; Value1: Unknown; Value2: 10V; TaMin_C: -55; TaMax_C: 125; AEC Category: Q200; SizeArea_mm2: 1.28; SizeAreaWB_mm2: 4.68; SizeX_mm: 1.6; SizeY_mm: 0.8; SizeZ_mm: 1
C63 = C1005X7R1C224K050BC: CAP, CERM, 0.22 µF, 16 V, +/- 10%, X7R, 0402; Manufacturer: TDK; Polarized: N; CompType: Capacitor; U/M: EA; Cap_F: 0.00000022; Tolerance_%: 10; VDC_V: 16; TaMin_C: -55; TaMax_C: 125; Value: 0.22uF; Value1: Unknown; Value2: 16V; AEC Category: Q200; SizeArea_mm2: 0.5; SizeAreaWB_mm2: 3; SizeX_mm: 1; SizeZ_mm: 0.6
C64 = C1005X7R1C224K050BC: CAP, CERM, 0.22 µF, 16 V, +/- 10%, X7R, 0402; Manufacturer: TDK; Polarized: N; CompType: Capacitor; Value: 0.22uF; U/M: EA; Cap_F: 0.00000022; Tolerance_%: 10; Value1: Unknown; VDC_V: 16; Value2: 16V; TaMin_C: -55; TaMax_C: 125; AEC Category: Q200; SizeArea_mm2: 0.5; SizeAreaWB_mm2: 3; SizeX_mm: 1; SizeZ_mm: 0.6
C65 C66 = GRM1555C1H180JA01D: CAP, CERM, 18 pF, 50 V, +/- 5%, C0G/NP0, 0402; Manufacturer: MuRata; Polarized: N; CompType: Capacitor; Value: 18pF; U/M: EA; Cap_F: 0.000000000018; Tolerance_%: 5; Value1: Unknown; VDC_V: 50; Value2: 50V; TaMin_C: -55; TaMax_C: 125; AEC Category: Q200; SizeArea_mm2: 0.5; SizeAreaWB_mm2: 3; SizeX_mm: 1; SizeZ_mm: 0.6
C67 = GRM155R71C104KA88D: as C54 on sheet LDC_CLOCK
C68 = C0603C225K8PACTU: CAP, CERM, 2.2 µF, 10 V, +/- 10%, X5R, 0603; Manufacturer: Kemet; Polarized: N; CompType: Capacitor; Value: 2.2uF; U/M: EA; Cap_F: 0.0000022; Tolerance_%: 10; Value1: Unknown; Value2: 10V; TaMin_C: -55; TaMax_C: 85; AEC Category: Q200; SizeArea_mm2: 1.28; SizeAreaWB_mm2: 4.68; SizeX_mm: 1.6; SizeY_mm: 0.8; SizeZ_mm: 1
C69 = C1005X7R1C103K050BA: as C101 on sheet LDC_CLOCK
C70 C72 C74 = GRM188R61A106ME69D: CAP, CERM, 10 µF, 10 V, +/- 20%, X5R, 0603; Manufacturer: MuRata; Polarized: N; CompType: Capacitor; Value: 10uF; U/M: EA; Cap_F: 0.00001; Tolerance_%: 20; Value1: Unknown; VDC_V: 10; Value2: 10V; TaMin_C: -55; TaMax_C: 85; SizeArea_mm2: 1.28; SizeAreaWB_mm2: 4.68; SizeX_mm: 1.6; SizeY_mm: 0.8; SizeZ_mm: 1; AEC Category: Q200
C73 C75 = GRM155R61A105KE15D: as C102 on sheet LDC_CLOCK
C78 = C0603X222K5RACTU: CAP, CERM, 2200 pF, 50 V, +/- 10%, X7R, 0603; Manufacturer: Kemet; Polarized: N; CompType: Capacitor; Value: 2200pF; U/M: EA; Cap_F: 0.0000000022; Tolerance_%: 10; Value1: Unknown; VDC_V: 50; Value2: 50V; TaMin_C: -55; TaMax_C: 125; AEC Category: Q200; SizeArea_mm2: 1.28; SizeAreaWB_mm2: 4.68; SizeX_mm: 1.6; SizeY_mm: 0.8; SizeZ_mm: 1
D17 = LG L29K-G2J1-24-Z: LED, Green, SMD; Manufacturer: OSRAM; Vf_V: 1.7; Value2: 1.7V; Io_A: 0.002; Tjmax_C: 110; Value1: W; U/M: EA
D18 = LS L29K-G1J2-1-Z: LED, Red, SMD; Manufacturer: OSRAM; Vf_V: 1.8; Value2: 1.8V; Io_A: 0.02; Vr_V: 12; Tjmax_C: 110; Value1: W; Angle: 160; U/M: EA
D19 = MMSZ5232B-7-F: Diode, Zener, 5.6 V, 500 mW, SOD-123; Manufacturer: Diodes Inc.; U/M: EA; Power_W: 0.5; Vz_V: 5.6; Value1: 0.5W; RJA_CperW: 350; SymbolCreator: a0412235; AEC Category: Q101; SizeAreaWB_mm2: 13.095; SizeArea_mm2: 6.545; SizeX_mm: 3.85; SizeY_mm: 1.7; SizeZ_mm: 1.35
FB1 = MMZ1608B102CTA00: Ferrite Bead, 1000 ohm @ 100 MHz, 0.3 A, 0603; Manufacturer: TDK; DCR_ohm: 0.6; Imax_A: 0.3; Value1: 0.6 ohm; Value2: 0.3A; ZTyp@100MHz_Ohm: 1000
J1 = 10118193-0001LF: Connector, Receptacle, USB Micro B, R/A, SMT; Manufacturer: FCI; SymbolCreator: a0411947; Pitch_mm: 0.65; Gender: Female; Row_Count: 1; ContactFinish: Gold
J2 = HTSW-103-07-G-S: Header, 100mil, 3x1, Gold, TH; Manufacturer: Samtec; SymbolCreator: a0799628
J3 = ZX62R-B-5P: Connector, Receptacle, Micro-USB Type B, SMT; Manufacturer: Hirose Electric Co. Ltd.; SymbolCreator: a0799628
LS1 = CPT-9019S-SMT-TR: PIEZO BUZZER TRANSDUCER, 4kHz, SMD; Manufacturer: CUI Inc.; SymbolCreator: a0411947; SizeAreaWB_mm2: 121; SizeArea_mm2: 81; SizeX_mm: 9; SizeZ_mm: 2.4
MG1 = C10-000: 10mm Linear Resonant Actuator - 3mm Type, TH; Manufacturer: Precision Microdrives Limited; SymbolCreator: Altium; SizeAreaWB_mm2: 204; SizeArea_mm2: 150; SizeX_mm: 10; SizeY_mm: 15; SizeZ_mm: 3.2
R60 R61 = CRCW04021K00JNED: RES, 1.0 k, 5%, 0.063 W, 0402; Manufacturer: Vishay-Dale; CompType: Resistor; Value: 1.0k; Res_ohm: 1000; Value_Code: 1k00; Tolerance_%: 5; Power_W: 0.063; Value2: 0.063W; VDC_V: 50; TempCo: 200 ppm/C; EIA_Code: E24; U/M: EA; AEC Category: Q200; SizeArea_mm2: 0.5; SizeX_mm: 1; SizeZ_mm: 0.6
R66 R67 = CRCW040233R0JNED: RES, 33, 5%, 0.063 W, 0402; Manufacturer: Vishay-Dale; CompType: Resistor; Value: 33; Value_Code: 33R0; Tolerance_%: 5; Power_W: 0.063; Value2: 0.063W; VDC_V: 50; TempCo: 200 ppm/C; EIA_Code: E24; U/M: EA; AEC Category: Q200; SizeArea_mm2: 0.5; SizeX_mm: 1; SizeZ_mm: 0.6
R68 = CRCW04021M00JNED: RES, 1.0 M, 5%, 0.063 W, 0402; Manufacturer: Vishay-Dale; CompType: Resistor; Value: 1.0Meg; Res_ohm: 1000000; Value_Code: 1M00; Tolerance_%: 5; Power_W: 0.063; Value2: 0.063W; VDC_V: 50; TempCo: 200 ppm/C; EIA_Code: E24; U/M: EA; AEC Category: Q200; SizeArea_mm2: 0.5; SizeX_mm: 1; SizeZ_mm: 0.6
R69 = CRCW04021K50JNED: RES, 1.5 k, 5%, 0.063 W, 0402; Manufacturer: Vishay-Dale; CompType: Resistor; Value: 1.5k; Res_ohm: 1500; Value_Code: 1k50; Tolerance_%: 5; Power_W: 0.063; Value2: 0.063W; VDC_V: 50; TempCo: 200 ppm/C; EIA_Code: E24; U/M: EA; AEC Category: Q200; SizeArea_mm2: 0.5; SizeX_mm: 1; SizeZ_mm: 0.6
R70 = RC0603FR-07390RL: RES, 390, 1%, 0.1 W, 0603; Manufacturer: Yageo America; CompType: Resistor; Value: 390; Value_Code: 390R; Tolerance_%: 1; Power_W: 0.1; Value2: 0.1W; VDC_V: 150; TempCo: 200 ppm/C; U/M: EA; AEC Category: Q200; SizeArea_mm2: 1.28; SizeX_mm: 1.6; SizeY_mm: 0.8
R71 = CRCW040233K0JNED: RES, 33 k, 5%, 0.063 W, 0402; Manufacturer: Vishay-Dale; CompType: Resistor; Res_ohm: 33000; Value_Code: 33k0; Tolerance_%: 5; Power_W: 0.063; Value2: 0.063W; VDC_V: 50; TempCo: 200 ppm/C; EIA_Code: E24; U/M: EA; AEC Category: Q200; SizeArea_mm2: 0.5; SizeX_mm: 1; SizeZ_mm: 0.6
R95-R98 = CRCW04024K70JNED: RES, 4.7 k, 5%, 0.063 W, 0402; Manufacturer: Vishay-Dale; CompType: Resistor; Value: 4.7k; Res_ohm: 4700; Value_Code: 4k70; Tolerance_%: 5; Power_W: 0.063; Value2: 0.063W; VDC_V: 50; TempCo: 200 ppm/C; EIA_Code: E24; U/M: EA; AEC Category: Q200; SizeArea_mm2: 0.5; SizeX_mm: 1; SizeZ_mm: 0.6
TP1-TP3 = 5015: Test Point, Miniature, SMT; Manufacturer: Keystone; CompType: Test Point Loop
U7 = MSP430F5528IRGCT: 25 MHz Mixed Signal Microcontroller with 128 KB Flash, 8192 B SRAM and 47 GPIOs, -40 to 85 degC, 64-pin QFN (RGC), Green (RoHS & no Sb/Br); Alternate Manufacturer: Texas Instruments; Alternate PartNumber: Equivalent; ADC: 12-bit SAR; ADC Channels: 16; Brown Out Reset: Yes; DMA: 3; Flash(KB): 128; Frequency(MHz): 25; GPIO: 47; Multiplier: 32x32; Pin/Package: 64DSBGA, 64VQFN, 80BGA MICROSTAR JUNIOR; SRAM(B): 8192; SubFamily: 5 Series; Timers - 16-bit: 4; USB: 1; USCI_A (UART/LIN/IrDA/SPI): 2
U8 = LP2985AIM5-3.3/NOPB: Micropower 150 mA Low-Noise Ultra Low-Dropout Regulator, 5-pin SOT-23, Pb-Free; Manufacturer: Texas Instruments; PackageTopMarking: L0RA*XTT; PowerWise: N; CompType: LDO IC
U9 = TPD4E004DRYR: ESD-Protection Array for High-Speed Data Interfaces, 4 Channels, -40 to +85 degC, 6-pin SON (DRY), Green (RoHS & no Sb/Br); Manufacturer: Texas Instruments; Alternate PartNumber: Equivalent; 1394 / Firewire: TRUE; Breakdown Voltage(Min)(V): 6; IEC 61000-4-2 Air-Gap(+/- kV): 12; IEC 61000-4-2 Contact(+/- kV): 8; IO Capacitance(Typ)(pF): 1.6; IO Leakage Current(nA): 1; SubFamily: ESD Solution
U10 = DRV2605LDGS: Haptic Driver for LRA and ERM With Built-In Library and Smart Loop Architecture, DGS0010A (VSSOP-10); Manufacturer: Texas Instruments; SymbolCreator: a0411947; CompType: IC; U/M: EA; SizeArea_mm2: 14.7; SizeAreaWB_mm2: 23.6; SizeX_mm: 4.9; SizeY_mm: 3; SizeZ_mm: 1.1
Y1 = ABM8-24.000MHZ-B2-T: Crystal, 24.000MHz, 18pF, SMD; Manufacturer: Abracon Corporation; SymbolCreator: a0412235; U/M: EA; TaMin_C: -20; TaMax_C: 70; Frequency Stability: ±50ppm

## Sheet TIDA-01102A_COVER.SchDoc
size 431 x 279 mm; Date: Not shown in title block; ApprovedBy: Not shown in title block; CheckedBy: Not shown in title block; Author: Not shown in title block; CompanyName: Not shown in title block; Engineer: Not shown in title block; Organization: Not shown in title block; Address1: Not shown in title block; Address2: Not shown in title block; Address3: Not shown in title block; Address4: Not shown in title block; DocumentNumber: 1; Revision: Use project parameter SCH_Rev; SheetNumber: 1; SheetTotal: 9; PageSetup: Record=PageOptions¦CenterHorizontal=True¦CenterVertical=True¦PrintScale=1.00¦XCorrection=1.00¦YCorrection=1.00¦PrintKind=0¦BorderSize=5000000¦LeftOffset=0¦BottomOffset=0¦Orientation=2¦PaperLength=1000¦PaperWidth=1000¦Scale=100¦PaperSource=15¦PrintQuality=600¦MediaType=1¦DitherType=10¦PaperKind=Letter¦PrintScaleMode=1
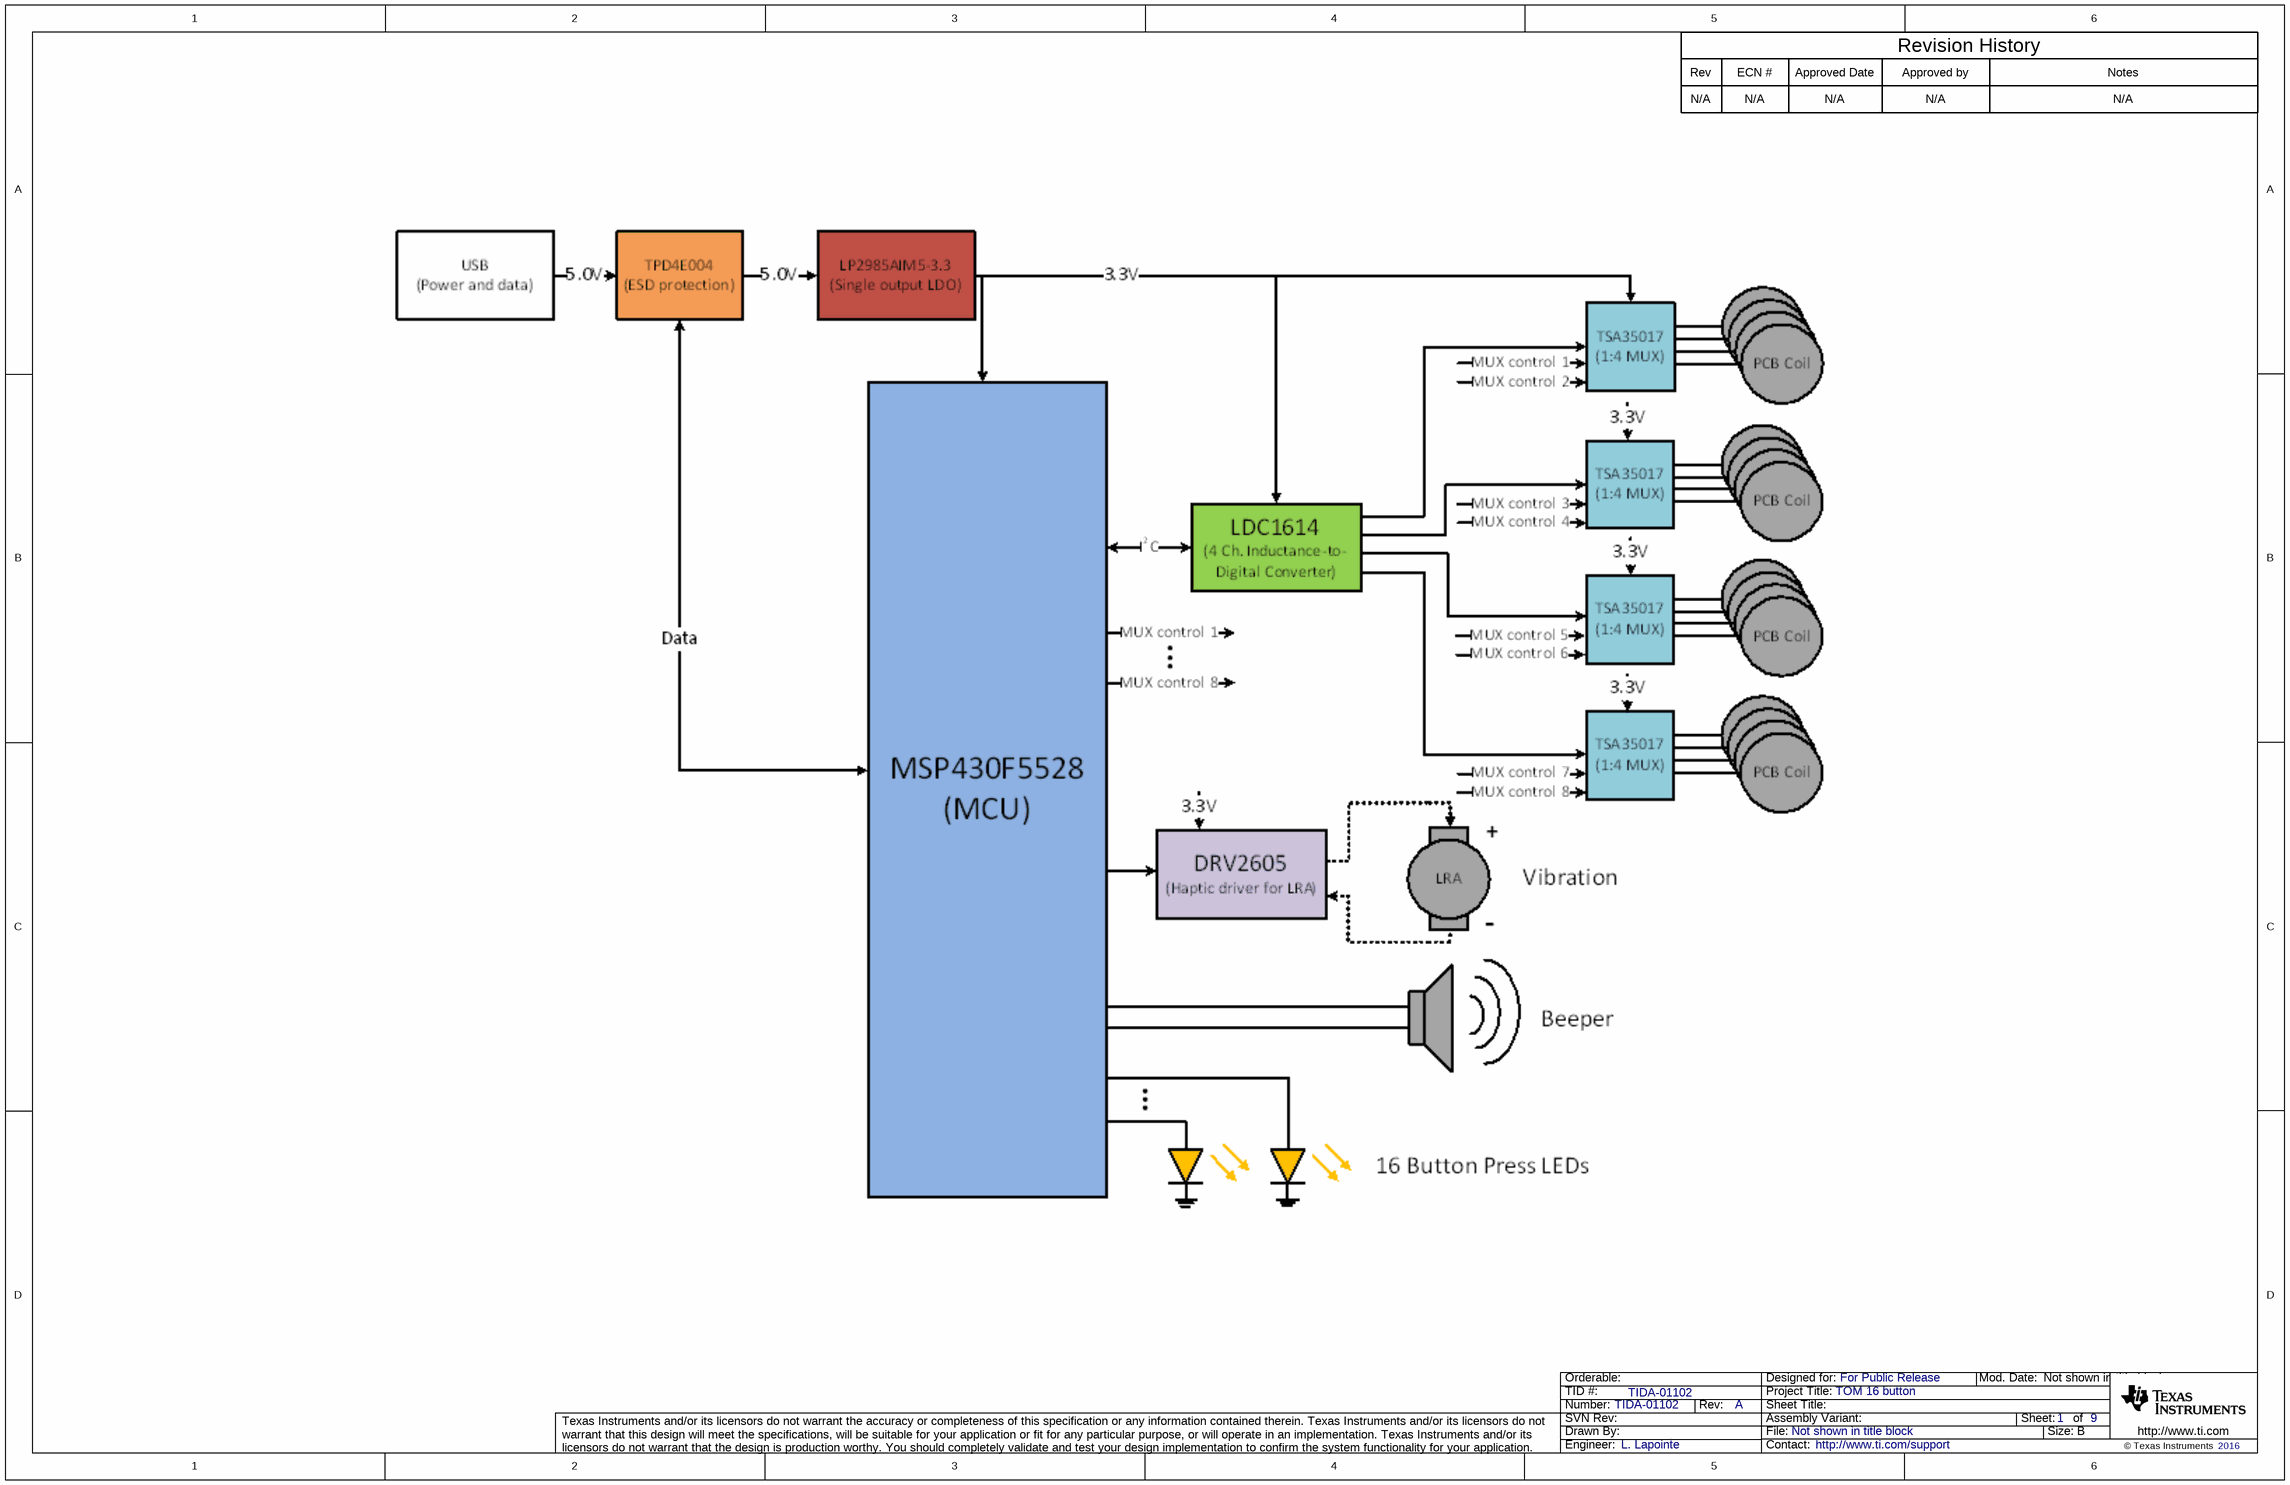
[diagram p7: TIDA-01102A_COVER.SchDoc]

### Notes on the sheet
- Rev
- N/A
- ECN #
- Approved Date
- Approved by
- Revision History
- Notes

## Sheet TIDA-01102A_Hardware.SchDoc
size 431 x 279 mm; Date: Not shown in title block; ApprovedBy: Not shown in title block; CheckedBy: Not shown in title block; Author: Not shown in title block; CompanyName: Not shown in title block; Engineer: Not shown in title block; Organization: Not shown in title block; Address1: Not shown in title block; Address2: Not shown in title block; Address3: Not shown in title block; Address4: Not shown in title block; DocumentNumber: 1; Revision: Use project parameter SCH_Rev; SheetNumber: 9; SheetTotal: 9; PageSetup: Record=PageOptions¦CenterHorizontal=True¦CenterVertical=True¦PrintScale=1.00¦XCorrection=1.00¦YCorrection=1.00¦PrintKind=0¦BorderSize=5000000¦LeftOffset=0¦BottomOffset=0¦Orientation=2¦PaperLength=1000¦PaperWidth=1000¦Scale=100¦PaperSource=15¦PrintQuality=600¦MediaType=1¦DitherType=10¦PaperKind=Letter¦PrintScaleMode=1
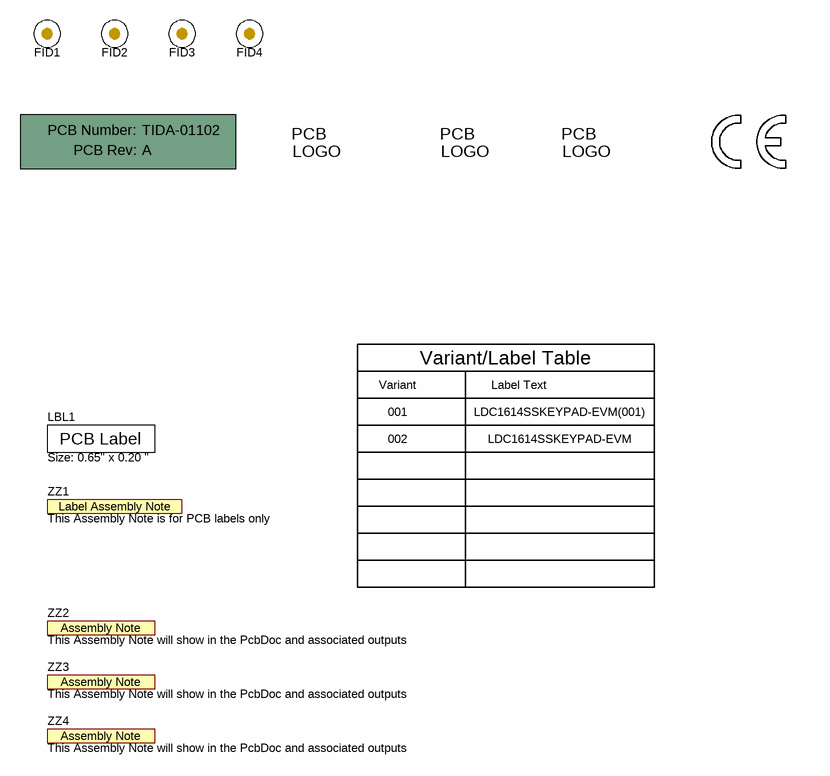
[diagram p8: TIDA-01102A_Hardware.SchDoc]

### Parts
!PCB  Printed Circuit Board  (value not drawn)  (mechanical)
FID1  Fiducial  [Fiducial10-30]  (value not drawn)
FID2  Fiducial  [Fiducial10-30]  (value not drawn)
FID3  Fiducial  [Fiducial10-30]  (value not drawn)
FID4  Fiducial  [Fiducial10-30]  (value not drawn)
LBL1  Size: 0.65" x 0.20 "  [Label_650x200]
Logo1  Texas Instruments  [TI_Stacked_SolderMask_Medium]  (value not drawn)  (no BOM)
Logo2  Pb-Free Symbol  [Pb-Free_Overlay_Medium]  (value not drawn)  (no BOM)
Logo3  FCC disclaimer  [FCC_disclaimer]  (value not drawn)  (no BOM)
LOGO4  CE Mark  [CE_Mark_5mm]  (value not drawn)  (no BOM)
ZZ1  This Assembly Note is for PCB labels only  [AssemblyNoteLabel]  (no BOM)
ZZ2  This Assembly Note will show in the PcbDoc and associated outputs  [AssemblyNote]  (no BOM)
ZZ3  This Assembly Note will show in the PcbDoc and associated outputs  [AssemblyNote]  (no BOM)
ZZ4  This Assembly Note will show in the PcbDoc and associated outputs  [AssemblyNote]  (no BOM)

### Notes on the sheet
- Variant
- Variant/Label Table
- Label Text
- 001
- 002
- LDC1614SSKEYPAD-EVM
- LDC1614SSKEYPAD-EVM(001)

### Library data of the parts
!PCB = PCB: Manufacturer: Any; PartNumber: TIDA-01102; SymbolCreator: a0412235
FID1-FID4 = Fiducial: Fiducial mark.  There is nothing to buy or mount.; SymbolCreator: codlsc
LBL1 = THT-14-423-10: Thermal Transfer Printable Labels, 0.650" W x 0.200" H - 10,000 per roll; Manufacturer: Brady; SymbolCreator: a0412235; CompType: Label
Logo1 = TI_Logo: Texas Instrument Corporate Signature; SymbolCreator: a0412235
Logo2 = Pb-Free: SymbolCreator: a0412235
Logo3 = FCC_disclaimer: SymbolCreator: a0412235
LOGO4 = CE Mark: SymbolCreator: a0412235
ZZ1 = AssemblyNoteLabel: SymbolCreator: a0412235
ZZ2-ZZ4 = AssemblyNote: SymbolCreator: codlsc

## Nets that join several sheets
GND: COILS_1 (6 pins), COILS_2 (6 pins), COILS_3 (6 pins), COILS_4 (6 pins), LDC_CLOCK (8 pins), LED_ARRAY (16 pins), UCONTROLLER (52 pins)
VCC: COILS_1 (C5.1 U1.14), COILS_2 (C10.1 U2.14), COILS_3 (C15.1 U3.14), COILS_4 (C20.1 U4.14), LDC_CLOCK (6 pins), UCONTROLLER (18 pins)
AA0: COILS_1 (C22.2 U1.5), LDC_CLOCK (U11.9)
AA1: COILS_2 (C30.2 U2.5), LDC_CLOCK (U11.11)
AA2: COILS_3 (C38.2 U3.5), LDC_CLOCK (U11.13)
AA3: COILS_4 (C46.2 U4.5), LDC_CLOCK (U11.15)
BB0: COILS_1 (C23.2 U1.7), LDC_CLOCK (U11.10)
BB1: COILS_2 (C31.2 U2.7), LDC_CLOCK (U11.12)
BB2: COILS_3 (C39.2 U3.7), LDC_CLOCK (U11.14)
BB3: COILS_4 (C47.2 U4.7), LDC_CLOCK (U11.16)
GPIO1: LED_ARRAY (D1.1), UCONTROLLER (U7.1)
GPIO2: LED_ARRAY (D2.1), UCONTROLLER (U7.2)
GPIO3: LED_ARRAY (D3.1), UCONTROLLER (U7.3)
GPIO4: LED_ARRAY (D4.1), UCONTROLLER (U7.4)
GPIO5: LED_ARRAY (D5.1), UCONTROLLER (U7.5)
GPIO6: LED_ARRAY (D6.1), UCONTROLLER (U7.6)
GPIO7: LED_ARRAY (D7.1), UCONTROLLER (U7.7)
GPIO8: LED_ARRAY (D8.1), UCONTROLLER (U7.8)
GPIO9: LED_ARRAY (D9.1), UCONTROLLER (U7.18)
GPIO10: LED_ARRAY (D10.1), UCONTROLLER (U7.19)
GPIO11: LED_ARRAY (D11.1), UCONTROLLER (U7.20)
GPIO12: LED_ARRAY (D12.1), UCONTROLLER (U7.21)
GPIO13: LED_ARRAY (D13.1), UCONTROLLER (U7.22)
GPIO14: LED_ARRAY (D14.1), UCONTROLLER (U7.23)
GPIO15: LED_ARRAY (D15.1), UCONTROLLER (U7.24)
GPIO16: LED_ARRAY (D16.1), UCONTROLLER (U7.25)
LDC_INT: LDC_CLOCK (U11.5), UCONTROLLER (U7.30)
SCL: LDC_CLOCK (U11.1), UCONTROLLER (R96.2 U7.35)
SDA: LDC_CLOCK (U11.2), UCONTROLLER (R95.2 U7.34)
SS0: COILS_1 (U1.12), UCONTROLLER (U7.32)
SS0: COILS_2 (U2.12), COILS_3 (U3.12), COILS_4 (U4.12)
SS1: COILS_1 (U1.16), UCONTROLLER (U7.33)
SS1: COILS_2 (U2.16), COILS_3 (U3.16), COILS_4 (U4.16)

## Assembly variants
001: not fitted C22 C23 C30 C31 C38 C39 C46 C47 C102 J2 J3 L1 L2 L3 L4 L5 L6 L7 L8 L9 L10 L11 L12 L13 L14 L15 L16 TP1 TP2 TP3; alternate parts C1 -> GRM155R71H102KA01D, C2 -> GRM155R71H102KA01D, C3 -> GRM155R71H102KA01D, C4 -> GRM155R71H102KA01D, C6 -> GRM155R71H102KA01D, C7 -> GRM155R71H102KA01D, C8 -> GRM155R71H102KA01D, C9 -> GRM155R71H102KA01D, C11 -> GRM155R71H102KA01D, C12 -> GRM155R71H102KA01D, C13 -> GRM155R71H102KA01D, C14 -> GRM155R71H102KA01D, C16 -> GRM155R71H102KA01D, C17 -> GRM155R71H102KA01D, C18 -> GRM155R71H102KA01D, C19 -> GRM155R71H102KA01D
002: not fitted C102 J2 J3 L1 L2 L3 L4 L5 L6 L7 L8 L9 L10 L11 L12 L13 L14 L15 L16 TP1 TP2 TP3; alternate parts C1 -> GRM155R71H681KA01D, C2 -> GRM155R71H681KA01D, C3 -> GRM155R71H681KA01D, C4 -> GRM155R71H681KA01D, C6 -> GRM155R71H681KA01D, C7 -> GRM155R71H681KA01D, C8 -> GRM155R71H681KA01D, C9 -> GRM155R71H681KA01D, C11 -> GRM155R71H681KA01D, C12 -> GRM155R71H681KA01D, C13 -> GRM155R71H681KA01D, C14 -> GRM155R71H681KA01D, C16 -> GRM155R71H681KA01D, C17 -> GRM155R71H681KA01D, C18 -> GRM155R71H681KA01D, C19 -> GRM155R71H681KA01D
